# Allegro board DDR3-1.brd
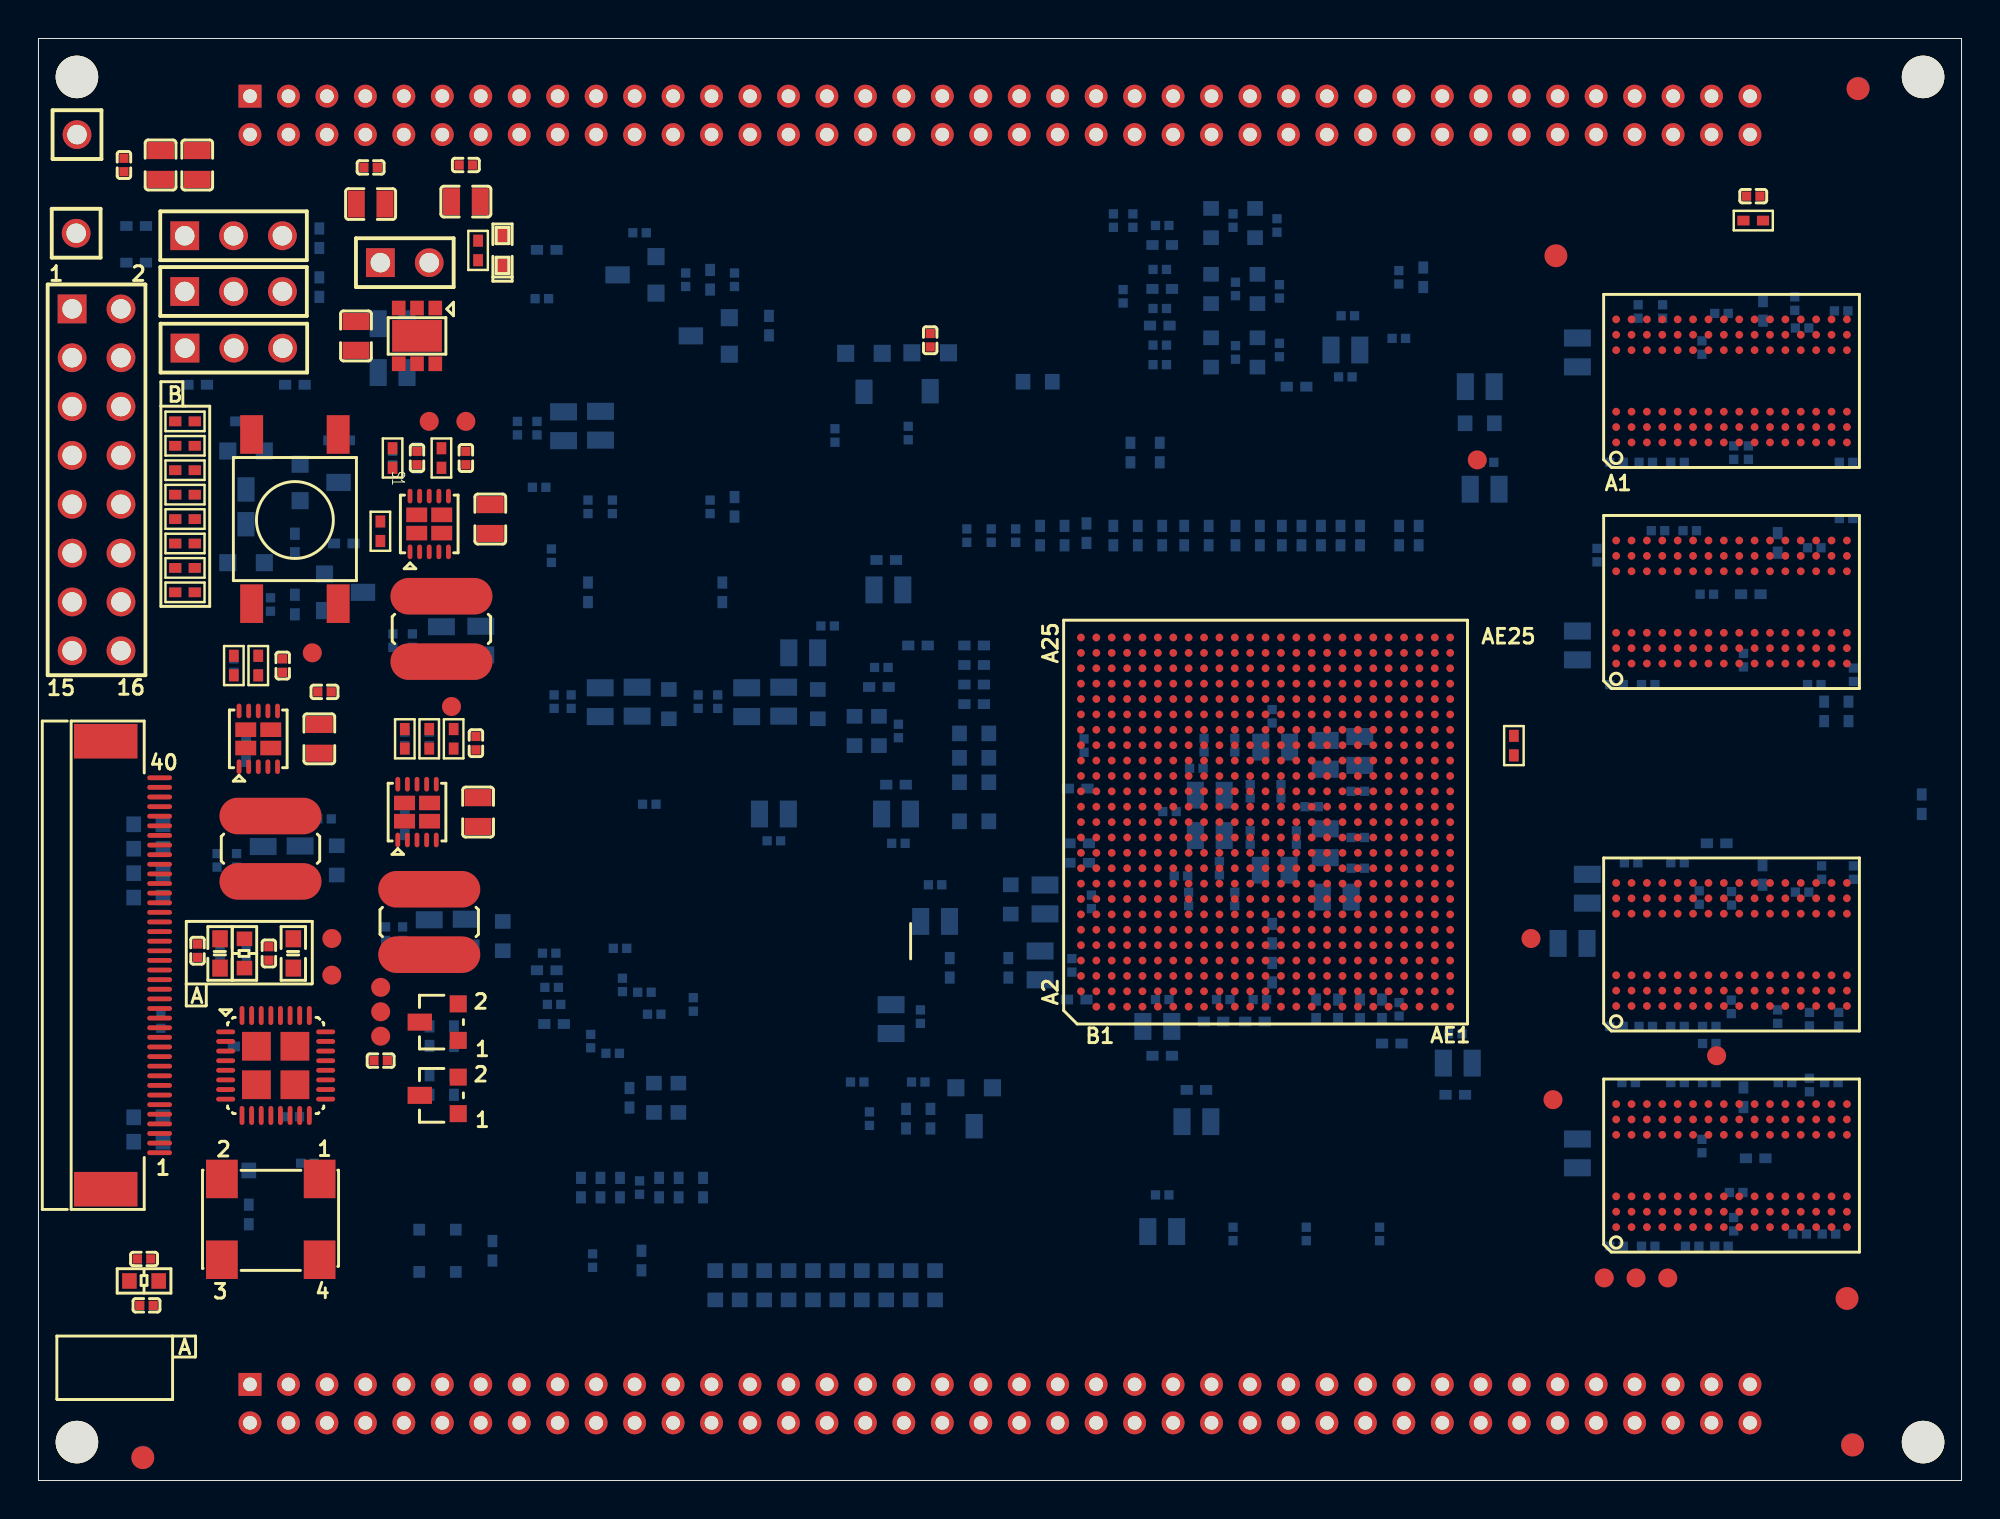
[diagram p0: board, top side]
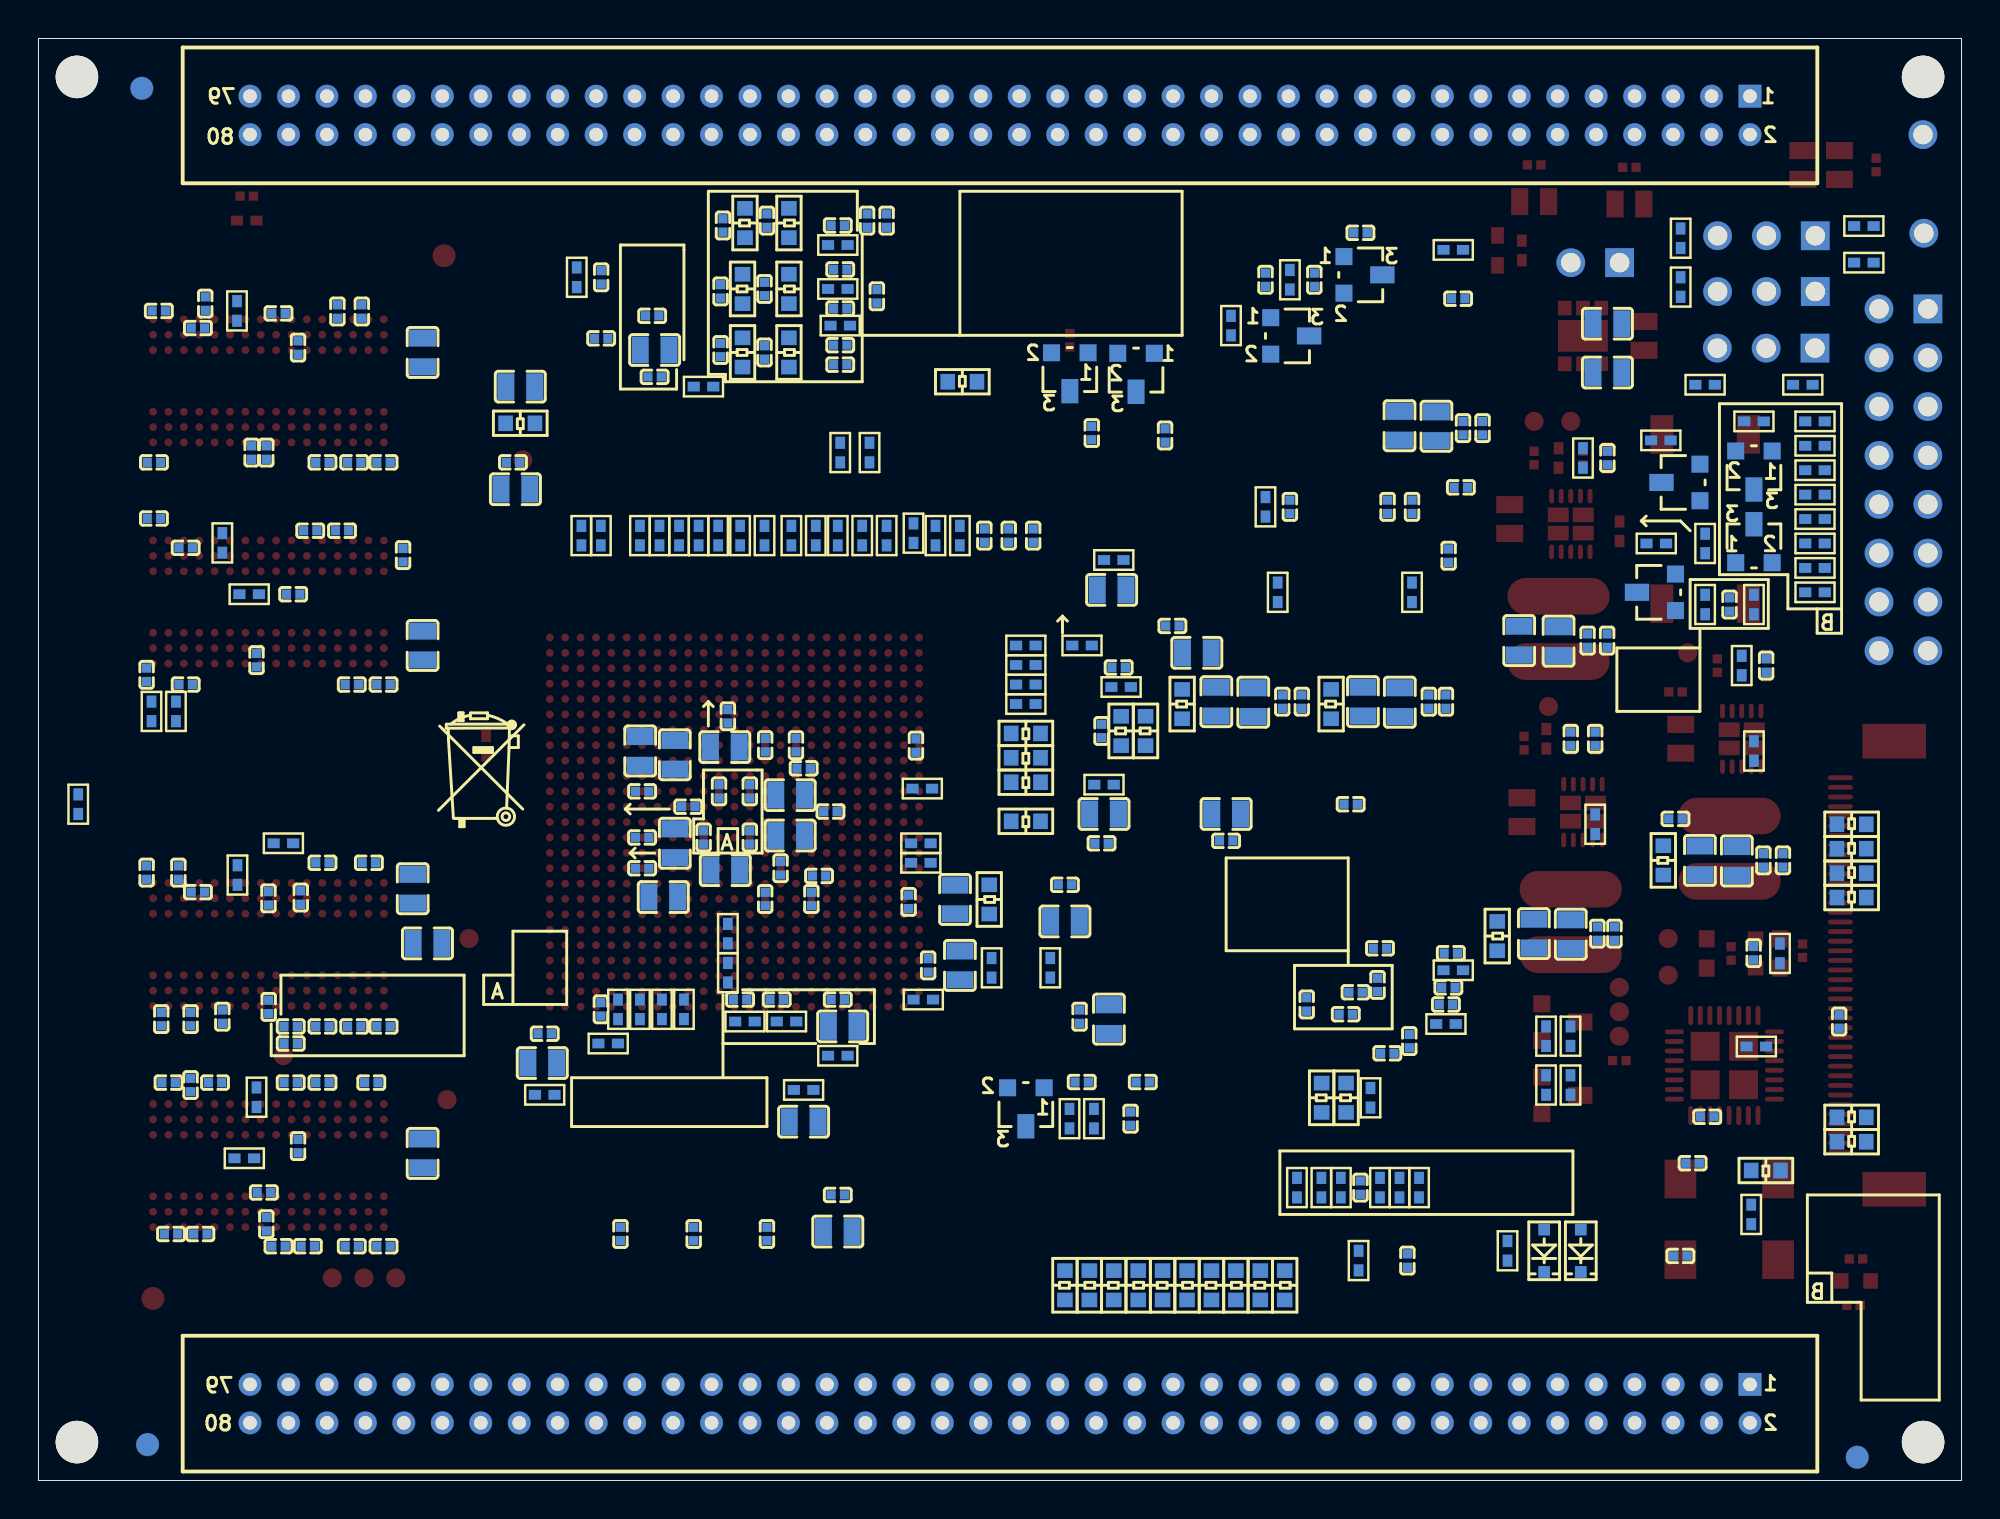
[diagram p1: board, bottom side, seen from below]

Outline 100 x 75 mm; copper layers: TOP, GND02, ART03, ART04, POWER05, ART06, GND07, BOTTOM. Coordinates in mm from the lower left corner of the outline.
Outline path: 0,75 0,0 ; 0,75 100,75 ; 0,75 0,0 ; 0,75 100,75 ; 0,0 100,0 ; 0,0 100,0 ; 100,75 100,10 ; 100,75 100,10 ; 100,0 100,10 ; 100,0 100,10

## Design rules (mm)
net group $$$4775: nets $$$4775 FEC_LED2
net group $$$7162: nets $$$7162 EIM_DA9
net group $$$7165: nets $$$7165 EIM_DA10
net group $$$7169: nets $$$7169 EIM_DA11
net group $$$7174: nets $$$7174 EIM_DA12
net group $$$7178: nets $$$7178 EIM_DA13
net group $$$7181: nets $$$7181 EIM_DA14
net group $$$7221: nets $$$7221 EIM_DA7
net group $$$7224: nets $$$7224 EIM_DA6
net group $$$7229: nets $$$7229 EIM_DA5
net group $$$7232: nets $$$7232 EIM_DA4
net group $$$9613: nets $$$9613 I2S_MCLK
net group $$$13768: nets $$$13768 VCC_5V
net group $$$14220: nets 1V3_CORE $$$14220
net group $$$14478: nets $$$14478 PWR_ON_REQ
net group $$$14578: nets $$$14578 $$$14580
net group $$$15209: nets 1V3_CORE23 $$$15209
net group $$$15211: nets $$$15211 $$$15212
net group $$$15334: nets 1V5 $$$15334
net group $$$15336: nets $$$15336 $$$15337
net group $$$15341: nets $$$15341 $$$15342
net group $$$16549: nets 1V3_SOC $$$16549
net group $$$16551: nets $$$16551 $$$16552
net group $$$17806: nets $$$17806 $$$17810
net group $$$18139: nets $$$18139 $$$18147
net group $$$22462: nets 1V8 $$$22462
net group $$$26219: nets $$$26219 SD3_CLK
net group $$$26224: nets $$$26224 SD4_CLK
net group $$$26282: nets $$$26282 SD1_CLK
net group $$$27898: nets $$$27898 PWM2
net group $$$32498: nets $$$32498 MIC
net group CSPI1_SSS0: nets CSPI1_SSS0 EIM_EB2
net group CSPI2_SSS0: nets CSPI2_SSS0 EIM_RW
net group CSPI2_SSS1: nets CSPI2_SSS1 EIM_LBA
net group DIFFPAIR10: nets USBOTG_DN USBOTG_DP
net group DIFFPAIR13: nets SATA_RXM SATA_RXP
net group DIFFPAIR14: nets SATA_TXM SATA_TXP
net group DIFFPAIR15: nets USB_H1_DN USB_H1_DP
net group DIFFPAIR16: nets PCIE_RXM PCIE_RXP
net group DIFFPAIR17: nets PCIE_TXM PCIE_TXP
net group DIFFPAIR18: nets PCIE_CLK_N PCIE_CLK_P
net group DIFFPAIR19: nets HDMI_CLKM HDMI_CLKP
net group DIFFPAIR20: nets HDMI_D0M HDMI_D0P
net group DIFFPAIR21: nets HDMI_D1M HDMI_D1P
net group DIFFPAIR22: nets HDMI_D2M HDMI_D2P
net group DIFFPAIR23: nets FEC_RX+ FEC_RX-
net group DIFFPAIR24: nets FEC_TX+ FEC_TX-
net group DIFFPAIR25: nets LVDS0_TX0_N LVDS0_TX0_P
net group DIFFPAIR26: nets LVDS0_TX2_N LVDS0_TX2_P
net group DIFFPAIR27: nets LVDS0_TX1_N LVDS0_TX1_P
net group DIFFPAIR28: nets LVDS0_TX3_N LVDS0_TX3_P
net group DIFFPAIR29: nets EXP2_27 EXP2_28
net group DIFFPAIR30: nets EXP2_29 EXP2_30
net group DIFFPAIR31: nets EXP2_31 EXP2_32
net group DIFFPAIR32: nets EXP2_33 EXP2_34
net group DIFFPAIR33: nets EXP2_35 EXP2_36
net group DIFFPAIR34: nets UART4_RXD UART4_TXD
net group DIFFPAIR35: nets LVDS1_TX0_N LVDS1_TX0_P
net group DIFFPAIR36: nets UART5_RXD UART5_TXD
net group DIFFPAIR37: nets LVDS1_TX1_N LVDS1_TX1_P
net group DIFFPAIR38: nets I2C3_SCL I2C3_SDA
net group DIFFPAIR39: nets LVDS1_TX2_N LVDS1_TX2_P
net group DIFFPAIR40: nets GP7_05 GP7_13
net group DIFFPAIR41: nets LVDS1_CLK_N LVDS1_CLK_P
net group DIFFPAIR42: nets LVDS1_TX3_N LVDS1_TX3_P
net group DIFFPAIR43: nets GP4_14 GP4_15
net group DIFFPAIR44: nets LVDS0_CLK_N LVDS0_CLK_P
net group SD1_CMD: nets SD1_CMD VCC_SD1
net group USB5V: nets USB5V USBH1_VBUS
net group 1V1: nets 1V1 HDMI_VP PCIE_VP PLL_1V1 SATA_VP
net group 2V5: nets 2V5 HDMI_VPH LVDS_2V5 PCIE_VPH SATA_VPH VCC_MIPI VDDHIGH_2V5
net group 5V_VGA: nets 5V_VGA DDC_SCL DDC_SDA
net group $$$12609: nets $$$6667 $$$6703 $$$9280 $$$12609 BATTERY VSNVS_3V0
net group $$$17664: nets $$$17664 $$$18017 I2C1_SCL I2C1_SDA NVCC_CSI
net group $$$22838: nets $$$22838 $$$22839 $$$22840
net group $$$24067: nets $$$3367 $$$24067 EIM_EB1 FEC_MDIO FEC_RST# VCC_FEC
net group $$$26032: nets $$$26032 $$$26035 USB5V_OTG
net group SD3_CD#: nets SD3_CD# SD3_CMD VCC_SD3

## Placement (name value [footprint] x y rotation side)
C1  CCAP  [C0805]  60.91 35.65 0 bottom
C2  CCAP  [C0402]  63.01 35.84 270 bottom
C3  CCAP  [C0402]  64.61 35.84 270 bottom
C4  CCAP  [C0402]  87.52 12.19 180 bottom
C5  CCAP  [C0402]  86.88 23.62 0 bottom
C6  CCAP  [C0805]  60.91 33.55 0 bottom
C7  CCAP  [C0805]  79.77 27.94 180 bottom
C8  CCAP  [C0402]  63.01 33.44 90 bottom
C9  CCAP  [C0402]  65.41 33.44 90 bottom
C10  CCAP  [C0402]  86.88 22.73 0 bottom
C11  CCAP  [C0402]  91.33 61.21 270 bottom
C12  CCAP  [C0805]  67.51 30.34 180 bottom
C13  CCAP  [C0402]  62.21 30.25 90 bottom
C14  CCAP  [C0402]  14.87 34.41 0 bottom
C15  CCAP  [C0402]  93.23 20.7 0 bottom
C16  CCAP  [C0402]  85.23 20.7 180 bottom
C17  CCAP  [C0805]  64.28 31.74 180 bottom
C18  CCAP  [C0805]  38.24 34.67 180 bottom
C19  CCAP  [C0402]  61.41 31.84 90 bottom
C20  CCAP  [C0402]  38.24 33.27 180 bottom
C21  CCAP  [C0402]  92.09 20.57 270 bottom
C22  CCAP  [C0402]  85.23 32.13 180 bottom
C23  CCAP  [C0805]  66.91 37.74 270 bottom
C24  CCAP  [C0805]  39.77 43.05 0 bottom
C25  CCAP  [C0402]  60.21 37.04 0 bottom
C26  CCAP  [C0402]  41.04 44.45 0 bottom
C27  CCAP  [C0402]  86.88 20.7 0 bottom
C28  CCAP  [C0402]  85.23 23.62 0 bottom
C29  CCAP  [C0805]  64.31 38.14 180 bottom
C31  CCAP  [C0402]  62.21 38.25 270 bottom
C32  CCAP  [C0402]  60.61 38.25 270 bottom
C33  CCAP  [C0402]  82.82 32.13 0 bottom
C34  CCAP  [C0402]  86.36 30.32 270 bottom
C35  CCAP  [C0805]  66.91 33.14 90 bottom
C36  CCAP  [C0805]  75.2 51.56 180 bottom
C37  CCAP  [C0402]  66.21 35.04 0 bottom
C38  CCAP  [C0402]  75.33 52.95 180 bottom
C39  CCAP  [C0402]  83.71 41.4 180 bottom
C41  CCAP  [C0805]  60.21 18.66 180 bottom
C42  CCAP  [C0402]  59.81 30.25 90 bottom
C44  CCAP  [C0402]  59.41 31.44 0 bottom
C47  CCAP  [C0402]  90.82 20.7 180 bottom
C48  CCAP  [C0402]  91.71 30.6 180 bottom
C49  CCAP  [C0402]  91.71 59.94 180 bottom
C50  CCAP  [C0402]  92.34 48.51 180 bottom
C51  CCAP  [C0402]  88.15 53.46 90 bottom
C52  CCAP  [C0402]  88.66 42.67 270 bottom
C53  CCAP  [C0402]  88.28 14.98 0 bottom
C54  CCAP  [C0402]  86.5 17.39 90 bottom
C55  CCAP  [C0402]  82.69 20.7 0 bottom
C56  CCAP  [C0402]  93.11 12.82 0 bottom
C57  CCAP  [C0402]  91.58 12.82 0 bottom
C58  CCAP  [C0402]  88.15 13.33 90 bottom
C59  CCAP  [C0402]  85.99 12.19 180 bottom
C60  CCAP  [C0402]  82.06 12.19 180 bottom
C61  CCAP  [C0402]  83.71 12.19 180 bottom
C62  CCAP  [C0805]  80.02 17.01 90 bottom
C63  CCAP  [C0402]  94.38 31.62 90 bottom
C64  CCAP  [C0402]  92.72 31.62 90 bottom
C65  CCAP  [C0402]  90.44 24.13 90 bottom
C66  CCAP  [C0402]  93.61 24 90 bottom
C67  CCAP  [C0402]  92.09 24 90 bottom
C68  CCAP  [C0402]  88.03 24.63 90 bottom
C69  CCAP  [C0402]  83.58 23.62 180 bottom
C70  CCAP  [C0402]  82.06 23.62 180 bottom
C71  CCAP  [C0402]  88.04 30.28 90 bottom
C72  CCAP  [C0805]  80.54 30.78 270 bottom
C73  CCAP  [C0402]  92.34 41.4 180 bottom
C74  CCAP  [C0402]  93.99 50.03 180 bottom
C75  CCAP  [C0402]  94.38 41.91 270 bottom
C76  CCAP  [C0402]  85.87 49.4 180 bottom
C77  CCAP  [C0402]  86.76 46.1 180 bottom
C78  CCAP  [C0402]  82.06 41.4 180 bottom
C79  CCAP  [C0402]  84.22 49.4 0 bottom
C80  CCAP  [C0402]  81.04 48.13 270 bottom
C81  CCAP  [C0402]  93.99 52.95 180 bottom
C82  CCAP  [C0805]  80.02 43.43 270 bottom
C83  CCAP  [C0402]  82.06 52.95 180 bottom
C84  CCAP  [C0402]  83.58 52.95 180 bottom
C85  CCAP  [C0402]  85.23 52.95 0 bottom
C86  CCAP  [C0402]  88.91 53.46 90 bottom
C87  CCAP  [C0402]  93.74 60.83 180 bottom
C88  CCAP  [C0402]  87.52 60.7 0 bottom
C89  CCAP  [C0402]  86.5 58.92 270 bottom
C90  CCAP  [C0402]  84.45 60.8 270 bottom
C91  CCAP  [C0402]  83.19 60.8 270 bottom
C92  CCAP  [C0805]  80.02 58.67 90 bottom
C93  CCAP  [C0402]  68.61 35.84 180 bottom
C94  CCAP  [C0402]  68.61 33.44 180 bottom
C95  CCAP  [C0402]  68.61 31.84 180 bottom
C99  CCAP  [C0805]  68.71 37.95 270 bottom
C100  CCAP  [C0402]  54.37 38.22 270 bottom
C101  CCAP  [C0402]  44.72 38.98 90 bottom
C102  CCAP  [C0402]  58.82 34.79 180 bottom
C103  CCAP  [C0402]  26.68 25.65 0 bottom
C104  CCAP  [C0402]  31.51 25.4 180 bottom
C105  CCAP  [C0402]  34.05 24.76 270 bottom
C106  CCAP  [C0402]  31.26 15.24 90 bottom
C107  CCAP  [C0402]  28.72 22.86 90 bottom
C108  CCAP  [C0402]  31.76 35.17 180 bottom
C109  CCAP  [C0402]  30.24 27.68 0 bottom
C110  CCAP  [C0402]  26.81 24.76 0 bottom
C111  CCAP  [C0402]  26.56 27.43 0 bottom
C112  CCAP  [C0402]  30.37 25.78 90 bottom
C113  CCAP  [C0402]  32.02 24.25 0 bottom
C114  CCAP  [C0402]  29.86 22.22 0 bottom
C115  CCAP  [C0805]  44.2 46.32 0 bottom
C116  CCAP  [C0402]  48.27 49.14 270 bottom
C117  CCAP  [C0402]  50.81 49.14 270 bottom
C118  CCAP  [C0402]  49.54 49.14 270 bottom
C120  CCAP  [C0402]  65.93 12.82 90 bottom
C122  CCAP  [C0402]  62.12 12.82 90 bottom
C124  CCAP  [C0402]  69.74 12.82 90 bottom
C126  CCAP  [C0402]  64.15 39.75 90 bottom
C127  CCAP  [C0402]  63.51 25.01 0 bottom
C128  CCAP  [C0805]  73.8 21.71 180 bottom
C129  CCAP  [C0402]  73.67 23.24 180 bottom
C130  CCAP  [C0402]  67.96 57.4 180 bottom
C131  CCAP  [C0402]  43.83 42.29 0 bottom
C132  CCAP  [C0402]  61.61 25.01 180 bottom
C133  CCAP  [C0805]  58.18 23.62 0 bottom
C134  CCAP  [C0402]  58.43 25.01 0 bottom
C135  CCAP  [C0805]  52.34 30.22 270 bottom
C136  CCAP  [C0402]  54.75 30.09 270 bottom
C137  CCAP  [C0805]  52.08 26.79 90 bottom
C138  CCAP  [C0402]  53.74 26.79 90 bottom
C139  CCAP  [C0805]  74.94 56.89 0 bottom
C140  CCAP  [C0402]  70.74 59.4 0 bottom
C141  CCAP  [C0402]  70.74 62.58 90 bottom
C144  CCAP  [C0402]  68.09 60.57 180 bottom
C145  CCAP  [C0805]  67.96 58.8 180 bottom
C152  CCAP  [C0402]  89.17 66.8 0 top
C153  CCAP  [C0805]  58.43 12.95 180 bottom
C154  CCAP  [C0402]  58.43 14.85 180 bottom
C155  CCAP  [C0805]  44.59 34.67 0 bottom
C156  CCAP  [C0402]  44.72 33.14 0 bottom
C157  CCAP  [C0805]  46.62 29.08 0 bottom
C158  CCAP  [C0402]  46.62 30.98 0 bottom
C159  CCAP  [C0402]  45.75 20.73 180 bottom
C160  CCAP  [C0402]  43.21 18.82 270 bottom
C161  CCAP  [C0402]  42.57 20.73 180 bottom
C162  CCAP  [C0402]  70.75 24.51 270 bottom
C163  CCAP  [C0402]  36.19 62.45 270 bottom
C164  CCAP  [C0805]  44.34 24 270 bottom
C165  CCAP  [C0402]  45.86 24.13 270 bottom
C166  CCAP  [C0402]  6.36 23.87 90 bottom
C167  CCAP  [C0402]  31.26 64.89 180 bottom
C168  CCAP  [C0402]  33.65 62.45 90 bottom
C173  CCAP  [C0402]  55.89 65.53 270 bottom
C174  CCAP  [C0402]  56.91 65.53 270 bottom
C175  CCAP  [C0402]  58.31 58.03 0 bottom
C176  CCAP  [C0402]  58.31 60.96 0 bottom
C177  CCAP  [C0402]  56.4 61.59 270 bottom
C178  CCAP  [C0402]  58.31 59.05 0 bottom
C179  CCAP  [C0402]  62.24 58.67 270 bottom
C180  CCAP  [C0402]  64.53 58.8 90 bottom
C181  CCAP  [C0402]  58.31 62.99 0 bottom
C182  CCAP  [C0402]  62.24 61.97 270 bottom
C183  CCAP  [C0402]  64.53 61.84 90 bottom
C184  CCAP  [C0402]  58.43 65.27 0 bottom
C185  CCAP  [C0402]  62.12 65.53 270 bottom
C186  CCAP  [C0402]  64.4 65.27 90 bottom
C190  CCAP  [C0402]  46.37 59.3 270 top
C191  CCAP  [C0402]  41.42 54.35 90 bottom
C192  CCAP  [C0402]  45.23 54.48 90 bottom
C193  CCAP  [C0402]  14.62 11.68 180 bottom
C194  CCAP  [C0402]  13.22 18.92 180 bottom
C195  CCAP  [C0402]  13.98 16.51 180 bottom
C196  CCAP  [C0603]  13.25 27.41 270 top
C197  CCAP  [C0402]  10.81 27.43 270 bottom
C198  CCAP  [C0402]  11.98 27.41 270 top
C199  CCAP  [C0402]  8.27 27.55 270 top
C200  CCAP  [C0603]  9.44 27.41 270 top
C201  CCAP  [C0402]  17.79 21.84 180 top
C202  CCAP  [C0402]  5.62 9.11 0 top
C203  CCAP  [C0805]  17.27 66.39 0 top
C204  CCAP  [C0402]  17.27 68.29 0 top
C205  CCAP  [C0402]  4.44 68.42 90 top
C206  CCAP  [C0805]  6.35 68.42 90 top
C207  CCAP  [C0805]  8.25 68.42 90 top
C208  CCAP  [C0402]  22.22 68.42 0 top
C209  CCAP  [C0805]  22.22 66.51 0 top
C210  CCAP  [C0402]  5.49 11.52 180 top
C211  CCAP  [C0805]  16.51 59.53 90 top
C212  CCAP  [C0805]  18.41 60.16 0 bottom
C213  CCAP  [C0805]  18.41 57.62 0 bottom
C214  CCAP  [C0402]  12.06 45.56 90 bottom
C215  CCAP  [C0402]  28.82 11.44 90 bottom
C218  CCAP  [C0402]  26.81 40.51 270 bottom
C219  CCAP  [C0402]  27.7 40.51 270 bottom
C220  CCAP  [C0805]  29.21 40.48 270 bottom
C221  CCAP  [C0805]  31.13 40.51 270 bottom
C222  CCAP  [C0402]  29.84 50.64 90 bottom
C223  CCAP  [C0402]  28.57 50.64 90 bottom
C224  CCAP  [C0805]  14.6 38.57 90 top
C225  CCAP  [C0402]  14.87 41.02 180 top
C226  CCAP  [C0402]  10.3 32.25 270 bottom
C227  CCAP  [C0402]  9.29 32.25 270 bottom
C228  CCAP  [C0805]  11.68 32.22 270 bottom
C229  CCAP  [C0805]  13.6 32.25 270 bottom
C230  CCAP  [C0402]  12.7 42.38 90 top
C231  CCAP  [C0402]  10.16 42.38 90 bottom
C234  CCAP  [C0402]  35.32 40.51 270 bottom
C235  CCAP  [C0402]  34.3 40.51 270 bottom
C236  CCAP  [C0805]  36.83 40.48 270 bottom
C237  CCAP  [C0805]  38.75 40.51 270 bottom
C239  CCAP  [C0402]  34.92 50.64 90 bottom
C240  CCAP  [C0805]  22.86 34.76 90 top
C241  CCAP  [C0402]  22.75 38.35 270 top
C242  CCAP  [C0402]  18.94 28.44 270 bottom
C243  CCAP  [C0402]  18.05 28.44 270 bottom
C244  CCAP  [C0805]  20.32 28.41 270 bottom
C245  CCAP  [C0805]  22.24 28.44 270 bottom
C246  CCAP  [C0402]  20.32 38.57 90 bottom
C247  CCAP  [C0402]  19.05 38.57 90 bottom
C248  CCAP  [C0805]  23.49 50 90 top
C249  CCAP  [C0402]  22.22 53.18 270 top
C250  CCAP  [C0402]  18.43 43.68 270 bottom
C251  CCAP  [C0402]  19.45 43.68 270 bottom
C252  CCAP  [C0805]  20.95 43.65 270 bottom
C253  CCAP  [C0805]  23 43.68 270 bottom
C254  CCAP  [C0402]  19.68 53.18 90 top
C255  CCAP  [C0402]  18.41 53.18 90 bottom
C257  CCAP  [C0402]  26.18 61.46 180 bottom
C258  CCAP  [C0402]  25.92 54.73 270 bottom
C259  CCAP  [C0402]  24.91 54.73 270 bottom
C260  CCAP  [C0805]  27.3 54.83 270 bottom
C261  CCAP  [C0805]  29.22 54.86 270 bottom
C263  CCAP  [C0402]  26.03 51.66 180 bottom
C265  CCAP  [C0402]  26.67 48.1 90 bottom
D3  BAT54C  [SOT_23]  34.92 59.53 270 bottom
D8  BAT54C  [SOT_23]  42.93 57.62 0 bottom
D9  BAT54C  [SOT_23]  46.37 57.65 0 bottom
D10  _LED_2P_  [D0603]  24.13 63.97 90 top
D11  DIODE  [SOD_323]  19.8 11.95 90 bottom
D12  DIODE  [SOD_323]  21.7 11.95 90 bottom
FB1  FEBEAD  [R0603]  50.56 30.22 270 bottom
FB2  FEBEAD  [R0603]  74.94 54.99 0 bottom
FB3  FEBEAD  [R0603]  51.96 57.15 180 bottom
FB4  FEBEAD  [R0603]  5.49 10.38 0 top
FB5  FEBEAD  [R0603]  10.71 27.41 90 top
FM1  -  [FIDUCIALMARK]  94.34 1.85 0 top
FM2  -  [FIDUCIALMARK]  94.61 72.39 0 top
FM3  -  [FIDUCIALMARK]  5.43 1.19 0 top
FM4  -  [FIDUCIALMARK]  94.05 9.47 0 top
FM*  -  [unnamed]  78.91 63.7 0 top
FM*#2  -  [unnamed]  94.63 72.41 180 bottom
FM*#3  -  [unnamed]  5.43 1.22 180 bottom
FM*#4  -  [unnamed]  94.33 1.88 180 bottom
J1  _HDR254_2X8_  [HDR254_2X8_A]  1.75 60.93 270 top
J2  _HDR254_3_  [JP254_3]  7.62 58.89 0 top
J3  _HDR254_3_  [JP254_3]  7.61 64.74 0 top
J4  _HDR254_3_  [JP254_3]  7.61 61.84 0 top
J5  _HDR200_2X40_  [HDR200_2X40]  11 72 0 bottom
J6  _HDR200_2X40_  [HDR200_2X40]  11 5 0 bottom
J7  _FPC_40_  [FPC40_P0_5]  6.3 26.8 270 top
J8  _HDR254_2_  [JP254_2]  17.78 63.34 90 top
J9  _HDR254_1_  [JP254_1]  2.01 70 0 top
J10  _HDR254_1_  [JP254_1]  1.96 64.87 0 top
L1  FEBEAD  [R0603]  60.97 58.67 270 bottom
L2  FEBEAD  [R0603]  63.39 58.67 90 bottom
L3  FEBEAD  [R0603]  60.97 61.97 270 bottom
L4  FEBEAD  [R0603]  63.39 61.97 90 bottom
L5  FEBEAD  [R0603]  60.97 65.4 270 bottom
L6  FEBEAD  [R0603]  63.26 65.4 90 bottom
L8  _IND_SMD_  [IND_SMD_5050]  12.06 32.86 90 top
L10  _IND_SMD_  [IND_SMD_5050]  20.32 29.05 90 top
L11  _IND_SMD_  [IND_SMD_5050]  20.95 44.29 90 top
MH1  _MOUNT_HOLE_  [MTH_1P2_2]  2 73 0 top
MH2  _MOUNT_HOLE_  [MTH_1P2_2]  2 2 0 top
MH3  _MOUNT_HOLE_  [MTH_1P2_2]  98 2 0 top
MH4  _MOUNT_HOLE_  [MTH_1P2_2]  98 73 0 top
NOREF  -  [#2]  74.44 37.08 180 bottom
Q1  BAT54C  [SOT_23]  48.66 19.43 0 bottom
Q3  BAT54C  [SOT_23]  20.83 23.84 90 top
Q4  BAT54C  [SOT_23]  20.83 20.03 90 top
Q5  FDC697P  [SOT_6]  19.68 59.53 180 top
Q6  BAT54C  [SOT_23]  14.6 51.91 90 bottom
Q7  BAT54C  [SOT_23]  10.79 48.73 180 bottom
Q8  BAT54C  [SOT_23]  10.79 52.54 0 bottom
Q9  BAT54C  [SOT_23]  15.87 46.19 90 bottom
R1  FEBEAD  [R0603]  32.78 40.38 90 bottom
R2  FEBEAD  [R0603]  15.51 32.25 90 bottom
R3  FEBEAD  [R0603]  40.53 40.38 90 bottom
R4  RES  [R0402]  60.21 20.32 180 bottom
R9  RES  [R0402]  88.66 19.93 270 bottom
R10  RES  [R0402]  89.65 31.49 270 bottom
R11  RES  [R0402]  90.44 48.76 270 bottom
R12  RES  [R0402]  89.68 60.83 270 bottom
R13  RES  [R0402]  97.93 35.17 270 bottom
R14  RES  [R0402]  76.72 38.22 90 top
R15  RES  [R0402]  94.12 40 90 bottom
R16  RES  [R0402]  92.85 40 270 bottom
R17  FEBEAD  [R0603]  24.14 28.32 270 bottom
R18  RES  [R0402]  89.3 16.76 180 bottom
R19  RES  [R0402]  89.04 46.1 180 bottom
R20  RES  [R0402]  48.66 41.4 180 bottom
R22  RES  [R0402]  48.66 40.38 180 bottom
R23  FEBEAD  [R0603]  48.66 38.86 0 bottom
R24  FEBEAD  [R0603]  48.66 37.59 0 bottom
R25  FEBEAD  [R0603]  43.7 38.98 90 bottom
R26  FEBEAD  [R0603]  42.43 38.98 90 bottom
R27  FEBEAD  [R0603]  48.66 34.29 0 bottom
R28  FEBEAD  [R0603]  48.66 36.32 0 bottom
R29  RES  [R0402]  26.43 26.54 0 bottom
R30  RES  [R0402]  30.73 19.91 270 bottom
R31  FEBEAD  [R0603]  33.27 19.91 90 bottom
R32  FEBEAD  [R0603]  32 19.91 90 bottom
R33  RES  [R0402]  26.81 23.74 0 bottom
R34  RES  [R0402]  29.22 15.24 270 bottom
R35  RES  [R0402]  30.24 15.24 270 bottom
R36  RES  [R0402]  32.27 15.24 270 bottom
R37  RES  [R0402]  33.29 15.24 270 bottom
R38  RES  [R0402]  28.21 15.24 270 bottom
R39  RES  [R0402]  34.56 15.24 270 bottom
R40  RES  [R0402]  67.71 49.14 90 bottom
R41  RES  [R0402]  53.35 49.14 90 bottom
R44  RES  [R0402]  54.04 35.99 180 bottom
R45  RES  [R0402]  48.66 42.41 180 bottom
R46  RES  [R0402]  44.08 47.87 0 bottom
R50  RES  [R0402]  53.99 25.01 0 bottom
R53  RES  [R0402]  45.73 43.43 0 bottom
R60  RES  [R0402]  63.26 23.87 0 bottom
R61  RES  [R0402]  73.67 20.06 180 bottom
R62  RES  [R0402]  64.15 28.44 270 bottom
R63  RES  [R0402]  64.15 26.41 90 bottom
R64  RES  [R0402]  65.42 56.89 0 bottom
R65  RES  [R0402]  43.7 41.27 0 bottom
R66  RES  [R0402]  61.1 23.87 180 bottom
R67  RES  [R0402]  58.43 22.09 0 bottom
R68  RES  [R0402]  50.43 26.67 90 bottom
R70  RES  [R0402]  70.75 49.14 90 bottom
R71  RES  [R0402]  68.72 49.14 270 bottom
R77  RES  [R0402]  72.01 62.58 270 bottom
R82  RES  [R0402]  89.17 65.53 180 top
R83  RES  [R0402]  44.59 36.19 0 bottom
R84  RES  [R0402]  47.39 26.67 90 bottom
R85  RES  [R0402]  54.12 32.13 180 bottom
R87  RES  [R0402]  45.11 18.82 90 bottom
R88  RES  [R0402]  46.38 18.82 90 bottom
R89  RES  [R0402]  70.37 22.73 0 bottom
R90  RES  [R0402]  37.99 60.07 90 bottom
R92  RES  [R0402]  34.92 62.45 270 bottom
R93  RES  [R0402]  54.12 33.14 180 bottom
R96  RES  [R0402]  69.86 24.51 90 bottom
R97  RES  [R0402]  68.72 24.51 90 bottom
R98  RES  [R0402]  67.58 24.51 90 bottom
R99  RES  [R0402]  66.44 24.51 90 bottom
R107  RES  [R0402]  56.78 53.46 270 bottom
R108  RES  [R0402]  60.85 49.14 270 bottom
R109  RES  [R0402]  58.31 53.46 270 bottom
R110  RES  [R0402]  62.24 49.14 270 bottom
R111  RES  [R0402]  7.62 52.54 180 bottom
R112  RES  [R0402]  7.62 52.54 180 top
R113  RES  [R0402]  7.62 55.08 180 bottom
R114  RES  [R0402]  7.62 55.08 180 top
R116  RES  [R0402]  65.67 49.14 90 bottom
R118  RES  [R0402]  7.62 46.19 180 bottom
R119  RES  [R0402]  7.62 46.19 180 top
R120  RES  [R0402]  7.62 48.73 180 bottom
R121  RES  [R0402]  7.62 48.73 180 top
R125  RES  [R0402]  58.43 49.14 270 bottom
R127  RES  [R0402]  55.89 49.14 270 bottom
R128  RES  [R0402]  57.16 49.14 270 bottom
R130  RES  [R0402]  54.5 49.27 270 bottom
R133  RES  [R0402]  59.58 49.14 270 bottom
R134  RES  [R0402]  63.51 49.14 270 bottom
R136  RES  [R0402]  48.66 43.43 0 bottom
R137  RES  [R0402]  52.08 49.14 270 bottom
R138  RES  [R0402]  7.62 51.27 0 bottom
R139  RES  [R0402]  7.62 51.27 0 top
R140  RES  [R0402]  7.62 53.81 0 bottom
R141  RES  [R0402]  7.62 53.81 0 top
R142  RES  [R0402]  66.69 49.14 270 bottom
R144  RES  [R0402]  7.62 47.46 0 bottom
R145  RES  [R0402]  7.62 47.46 0 top
R146  RES  [R0402]  7.62 50 0 bottom
R147  RES  [R0402]  7.62 50 0 top
R148  RES  [R0402]  64.66 49.14 270 bottom
R149  RES  [R0402]  8.25 56.99 0 bottom
R150  RES  [R0402]  5.08 65.24 180 bottom
R151  RES  [R0402]  5.08 63.34 180 bottom
R152  RES  [R0402]  13.33 56.99 180 bottom
R153  RES  [R0402]  14.6 64.61 90 bottom
R154  RES  [R0402]  14.6 62.07 270 bottom
R155  RES  [R0402]  58.31 60.07 0 bottom
R156  RES  [R0402]  58.43 61.97 0 bottom
R157  RES  [R0402]  58.43 64.26 0 bottom
R159  RES  [R0402]  21.6 23.11 90 bottom
R160  RES  [R0402]  20.33 23.11 270 bottom
R161  RES  [R0402]  21.6 20.57 270 bottom
R162  RES  [R0402]  20.33 20.57 90 bottom
R163  RES  [R0402]  10.67 22.57 0 bottom
R164  RES  [R0402]  10.94 13.84 90 bottom
R165  RES  [R0402]  9.44 27.41 270 bottom
R171  FEBEAD  [R0603]  35.19 10.16 270 bottom
R172  FEBEAD  [R0603]  37.73 10.16 270 bottom
R173  FEBEAD  [R0603]  40.27 10.16 270 bottom
R174  FEBEAD  [R0603]  42.81 10.16 270 bottom
R175  FEBEAD  [R0603]  45.35 10.16 270 bottom
R181  FEBEAD  [R0603]  36.46 10.16 90 bottom
R182  FEBEAD  [R0603]  39 10.16 90 bottom
R183  FEBEAD  [R0603]  41.54 10.16 90 bottom
R184  FEBEAD  [R0603]  44.08 10.16 90 bottom
R185  FEBEAD  [R0603]  46.62 10.16 90 bottom
R186  FEBEAD  [R0603]  5.71 17.62 180 bottom
R187  FEBEAD  [R0603]  5.71 18.89 180 bottom
R188  FEBEAD  [R0603]  5.71 30.32 180 bottom
R189  FEBEAD  [R0603]  5.71 31.59 180 bottom
R190  FEBEAD  [R0603]  5.71 32.86 180 bottom
R191  FEBEAD  [R0603]  5.71 34.13 180 bottom
R192  RES  [R0402]  15.64 54.1 0 bottom
R193  RES  [R0402]  13.33 48.73 90 bottom
R194  RES  [R0402]  15.87 48.73 0 bottom
R195  RES  [R0402]  13.33 45.56 270 bottom
R196  RES  [R0402]  10.79 55.08 180 bottom
R197  RES  [R0402]  10.79 45.56 270 bottom
R198  RES  [R0402]  22.86 63.97 90 top
R199  RES  [R0402]  23.61 11.95 270 bottom
R200  RES  [R0402]  31.36 11.44 90 bottom
R204  RES  [R0402]  28.57 46.19 270 bottom
R205  RES  [R0402]  11.43 42.38 90 top
R206  RES  [R0402]  11.43 42.38 90 bottom
R207  RES  [R0402]  10.16 42.38 270 top
R208  RES  [R0402]  10.79 37.94 270 bottom
R209  RES  [R0402]  36.19 50.64 90 bottom
R212  RES  [R0402]  35.56 46.19 270 bottom
R213  RES  [R0402]  20.32 38.57 90 top
R214  RES  [R0402]  21.59 38.57 90 top
R215  RES  [R0402]  19.05 38.57 270 top
R216  RES  [R0402]  19.05 34.13 270 bottom
R217  RES  [R0402]  19.68 53.18 90 bottom
R218  RES  [R0402]  20.95 53.18 90 top
R219  RES  [R0402]  18.41 53.18 270 top
R220  RES  [R0402]  17.78 49.37 270 top
R222  RES  [R0402]  26.43 64 0 bottom
R223  FEBEAD  [R0603]  10.17 16.12 0 bottom
R224  RES  [R0402]  87.26 33.14 180 bottom
R226  RES  [R0402]  71.77 49.14 90 bottom
S1  _TACT_4P_PUSHON_  [TACT_4P_PUSHON]  13.33 50 270 top
TP1  -  [TESTPOINT]  77.61 28.19 0 top
TP3  -  [TESTPOINT]  78.75 19.81 0 top
TP5  -  [TESTPOINT]  74.82 53.08 0 top
TP9  -  [TESTPOINT]  83.07 10.54 0 top
TP10  -  [TESTPOINT]  84.72 10.54 0 top
TP11  -  [TESTPOINT]  87.26 22.09 0 top
TP12  -  [TESTPOINT]  81.42 10.54 0 top
TP17  -  [TESTPOINT]  15.25 28.19 0 top
TP18  -  [TESTPOINT]  15.25 26.28 0 top
TP19  -  [TESTPOINT]  17.79 25.65 0 top
TP20  -  [TESTPOINT]  17.79 23.11 0 top
TP21  -  [TESTPOINT]  17.79 24.38 0 top
TP23  -  [TESTPOINT]  14.24 43.05 90 top
TP26  -  [TESTPOINT]  21.48 40.25 90 top
TP28  -  [TESTPOINT]  20.32 55.08 90 top
TP30  -  [TESTPOINT]  22.22 55.08 90 top
U1  IMX6Q  [IMX6Q_PBGA624_P0_8]  63.81 34.25 90 top
U2  _DDR3_16BIT_  [BGA96_P0_8]  88.04 16.38 90 top
U3  _DDR3_16BIT_  [BGA96_P0_8]  88.04 27.88 90 top
U4  _DDR3_16BIT_  [BGA96_P0_8]  88.04 45.69 90 top
U5  _DDR3_16BIT_  [BGA96_P0_8]  88.04 57.19 90 top
U11  BAT54C  [SOT_23]  31.11 62.7 270 bottom
U15  ALC5633Q  [QFN32]  12.33 21.59 90 top
U16  _OSC_4_  [OSC4_751]  12.08 13.58 180 top
U19  RT8055  [DFN_10_3X3]  11.43 38.57 0 top
U21  RT8055  [DFN_10_3X3]  19.68 34.76 0 top
U22  RT8055  [DFN_10_3X3]  20.32 49.75 0 top

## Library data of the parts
C1 C6 C7 C12 C17 C18 C23 C24 C29 C35 C36 C41 C62 C72 C82 C92 C99 C115 C128 C133 C135 C137 C139 C145 C153 C155 C157 C164 C203 C206 C207 C209 C211-C213 C220 C221 C224 C228 C229 C236 C237 C240 C244 C245 C248 C252 C253 C260 C261 = C0805
C2-C5 C8-C11 C13-C16 C19-C22 C25-C28 C31-C34 C37-C39 C42 C44 C47-C61 C63-C71 C73-C81 C83-C91 C93-C95 C100-C114 C116-C118 C120 C122 C124 C126 C127 C129-C132 C134 C136 C138 C140 C141 C144 C152 C154 C156 C158-C163 C165-C168 C173-C186 C190-C195 C197-C199 C201 C202 C204 C205 C208 C210 C214 C215 C218 C219 C222 C223 C225-C227 C230 C231 C234 C235 C239 C241-C243 C246 C247 C249-C251 C254 C255 C257-C259 C263 C265 = C0402
C196 C200 = C0603
D3 D8 D9 Q1 Q3 Q4 Q6-Q9 U11 = SOT_23
D10 = D0603
D11 D12 = SOD_323
FB1-FB5 L1-L6 R1-R3 R17 R23-R28 R31 R32 R171-R175 R181-R191 R223 = R0603
FM1-FM4 = FIDUCIALMARK
J1 = HDR254_2X8_A
J2-J4 = JP254_3
J5 J6 = HDR200_2X40
J7 = FPC40_P0_5
J8 = JP254_2
J9 J10 = JP254_1
L8 L10 L11 = IND_SMD_5050
MH1-MH4 = MTH_1P2_2
Q5 = SOT_6
R4 R9-R16 R18-R20 R22 R29 R30 R33-R41 R44-R46 R50 R53 R60-R68 R70 R71 R77 R82-R85 R87-R90 R92 R93 R96-R99 R107-R114 R116 R118-R121 R125 R127 R128 R130 R133 R134 R136-R142 R144-R157 R159-R165 R192-R200 R204-R209 R212-R220 R222 R224 R226 = R0402: signal model: R0402_RES
S1 = TACT_4P_PUSHON
TP1 TP3 TP5 TP9-TP12 TP17-TP21 TP23 TP26 TP28 TP30 = TESTPOINT
U1 = IMX6Q_PBGA624_P0_8
U2-U5 = BGA96_P0_8
U15 = QFN32
U16 = OSC4_751
U19 U21 U22 = DFN_10_3X3

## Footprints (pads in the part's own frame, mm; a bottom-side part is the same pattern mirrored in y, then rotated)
BGA96_P0_8
  round 0.406 smd: A1(-3.2,6) A2(-2.4,6) A3(-1.6,6) A7(1.6,6) A8(2.4,6) A9(3.2,6) B1(-3.2,5.2) B2(-2.4,5.2) B3(-1.6,5.2) B7(1.6,5.2) B8(2.4,5.2) B9(3.2,5.2) C1(-3.2,4.4) C2(-2.4,4.4) C3(-1.6,4.4) C7(1.6,4.4) C8(2.4,4.4) C9(3.2,4.4) D1(-3.2,3.6) D2(-2.4,3.6) D3(-1.6,3.6) D7(1.6,3.6) D8(2.4,3.6) D9(3.2,3.6) E1(-3.2,2.8) E2(-2.4,2.8) E3(-1.6,2.8) E7(1.6,2.8) E8(2.4,2.8) E9(3.2,2.8) F1(-3.2,2) F2(-2.4,2) F3(-1.6,2) F7(1.6,2) F8(2.4,2) F9(3.2,2) G1(-3.2,1.2) G2(-2.4,1.2) G3(-1.6,1.2) G7(1.6,1.2) G8(2.4,1.2) G9(3.2,1.2) H1(-3.2,0.4) H2(-2.4,0.4) H3(-1.6,0.4) H7(1.6,0.4) H8(2.4,0.4) H9(3.2,0.4) J1(-3.2,-0.4) J2(-2.4,-0.4) J3(-1.6,-0.4) J7(1.6,-0.4) J8(2.4,-0.4) J9(3.2,-0.4) K1(-3.2,-1.2) K2(-2.4,-1.2) K3(-1.6,-1.2) K7(1.6,-1.2) K8(2.4,-1.2) K9(3.2,-1.2) L1(-3.2,-2) L2(-2.4,-2) L3(-1.6,-2) L7(1.6,-2) L8(2.4,-2) L9(3.2,-2) M1(-3.2,-2.8) M2(-2.4,-2.8) M3(-1.6,-2.8) M7(1.6,-2.8) M8(2.4,-2.8) M9(3.2,-2.8) N1(-3.2,-3.6) N2(-2.4,-3.6) N3(-1.6,-3.6) N7(1.6,-3.6) N8(2.4,-3.6) N9(3.2,-3.6) P1(-3.2,-4.4) P2(-2.4,-4.4) P3(-1.6,-4.4) P7(1.6,-4.4) P8(2.4,-4.4) P9(3.2,-4.4) R1(-3.2,-5.2) R2(-2.4,-5.2) R3(-1.6,-5.2) R7(1.6,-5.2) R8(2.4,-5.2) R9(3.2,-5.2) T1(-3.2,-6) T2(-2.4,-6) T3(-1.6,-6) T7(1.6,-6) T8(2.4,-6) T9(3.2,-6)
C0402
  rect 0.483x0.483 smd: 1(-0.35,0) 2(0.35,0)
C0603
  rect 0.889x0.813 smd: 1(-0.762,0) 2(0.762,0)
C0805
  rect 0.889x1.397 smd: 1(-0.75,0) 2(0.75,0)
D0603
  rect 0.864x0.66 smd: 1(-0.78,0) 2(0.78,0)
DFN_10_3X3
  oval 0.254x0.762 smd: 1(-1,-1.45) 2(-0.5,-1.45) 3(0,-1.45) 4(0.5,-1.45) 5(1,-1.45) 6(1,1.45) 7(0.5,1.45) 8(0,1.45) 9(-0.5,1.45) 10(-1,1.45)
  rect 1.092x0.762 smd: 11(-0.65,-0.475) 12(0.65,-0.475) 13(-0.65,0.475) 14(0.65,0.475)
FIDUCIALMARK
  round 1.194 smd: 1(0,0)
FPC40_P0_5
  oval 0.254x1.295 smd: 1(9.75,0) 2(9.25,0) 3(8.75,0) 4(8.25,0) 5(7.75,0) 6(7.25,0) 7(6.75,0) 8(6.25,0) 9(5.75,0) 10(5.25,0) 11(4.75,0) 12(4.25,0) 13(3.75,0) 14(3.25,0) 15(2.75,0) 16(2.25,0) 17(1.75,0) 18(1.25,0) 19(0.75,0) 20(0.25,0) 21(-0.25,0) 22(-0.75,0) 23(-1.25,0) 24(-1.75,0) 25(-2.25,0) 26(-2.75,0) 27(-3.25,0) 28(-3.75,0) 29(-4.25,0) 30(-4.75,0) 31(-5.25,0) 32(-5.75,0) 33(-6.25,0) 34(-6.75,0) 35(-7.25,0) 36(-7.75,0) 37(-8.25,0) 38(-8.75,0) 39(-9.25,0) 40(-9.75,0)
  rect 1.803x3.302 smd: 41(11.65,-2.8) 42(-11.65,-2.8)
HDR200_2X40
  rect 1.194x1.194 hole 0.711: 1(0,0)
  round 1.194 hole 0.711: 2(0,2) 3(2,0) 4(2,2) 5(4,0) 6(4,2) 7(6,0) 8(6,2) 9(8,0) 10(8,2) 11(10,0) 12(10,2) 13(12,0) 14(12,2) 15(14,0) 16(14,2) 17(16,0) 18(16,2) 19(18,0) 20(18,2) 21(20,0) 22(20,2) 23(22,0) 24(22,2) 25(24,0) 26(24,2) 27(26,0) 28(26,2) 29(28,0) 30(28,2) 31(30,0) 32(30,2) 33(32,0) 34(32,2) 35(34,0) 36(34,2) 37(36,0) 38(36,2) 39(38,0) 40(38,2) 41(40,0) 42(40,2) 43(42,0) 44(42,2) 45(44,0) 46(44,2) 47(46,0) 48(46,2) 49(48,0) 50(48,2) 51(50,0) 52(50,2) 53(52,0) 54(52,2) 55(54,0) 56(54,2) 57(56,0) 58(56,2) 59(58,0) 60(58,2) 61(60,0) 62(60,2) 63(62,0) 64(62,2) 65(64,0) 66(64,2) 67(66,0) 68(66,2) 69(68,0) 70(68,2) 71(70,0) 72(70,2) 73(72,0) 74(72,2) 75(74,0) 76(74,2) 77(76,0) 78(76,2) 79(78,0) 80(78,2)
HDR254_2X8_A
  rect 1.499x1.499 hole 1.016: 1(0,0)
  round 1.499 hole 1.016: 2(0,2.54) 3(2.54,0) 4(2.54,2.54) 5(5.08,0) 6(5.08,2.54) 7(7.62,0) 8(7.62,2.54) 9(10.16,0) 10(10.16,2.54) 11(12.7,0) 12(12.7,2.54) 13(15.24,0) 14(15.24,2.54) 15(17.78,0) 16(17.78,2.54)
IMX6Q_PBGA624_P0_8
  round 0.406 smd: A2(-8.8,9.6) A3(-8,9.6) A4(-7.2,9.6) A5(-6.4,9.6) A6(-5.6,9.6) A7(-4.8,9.6) A8(-4,9.6) A9(-3.2,9.6) A10(-2.4,9.6) A11(-1.6,9.6) A12(-0.8,9.6) A13(0,9.6) A14(0.8,9.6) A15(1.6,9.6) A16(2.4,9.6) A17(3.2,9.6) A18(4,9.6) A19(4.8,9.6) A20(5.6,9.6) A21(6.4,9.6) A22(7.2,9.6) A23(8,9.6) A24(8.8,9.6) A25(9.6,9.6) AA1(-9.6,-6.4) AA2(-8.8,-6.4) AA3(-8,-6.4) AA4(-7.2,-6.4) AA5(-6.4,-6.4) AA6(-5.6,-6.4) AA7(-4.8,-6.4) AA8(-4,-6.4) AA9(-3.2,-6.4) AA10(-2.4,-6.4) AA11(-1.6,-6.4) AA12(-0.8,-6.4) AA13(0,-6.4) AA14(0.8,-6.4) AA15(1.6,-6.4) AA16(2.4,-6.4) AA17(3.2,-6.4) AA18(4,-6.4) AA19(4.8,-6.4) AA20(5.6,-6.4) AA21(6.4,-6.4) AA22(7.2,-6.4) AA23(8,-6.4) AA24(8.8,-6.4) AA25(9.6,-6.4) AB1(-9.6,-7.2) AB2(-8.8,-7.2) AB3(-8,-7.2) AB4(-7.2,-7.2) AB5(-6.4,-7.2) AB6(-5.6,-7.2) AB7(-4.8,-7.2) AB8(-4,-7.2) AB9(-3.2,-7.2) AB10(-2.4,-7.2) AB11(-1.6,-7.2) AB12(-0.8,-7.2) AB13(0,-7.2) AB14(0.8,-7.2) AB15(1.6,-7.2) AB16(2.4,-7.2) AB17(3.2,-7.2) AB18(4,-7.2) AB19(4.8,-7.2) AB20(5.6,-7.2) AB21(6.4,-7.2) AB22(7.2,-7.2) AB23(8,-7.2) AB24(8.8,-7.2) AB25(9.6,-7.2) AC1(-9.6,-8) AC2(-8.8,-8) AC3(-8,-8) AC4(-7.2,-8) AC5(-6.4,-8) AC6(-5.6,-8) AC7(-4.8,-8) AC8(-4,-8) AC9(-3.2,-8) AC10(-2.4,-8) AC11(-1.6,-8) AC12(-0.8,-8) AC13(0,-8) AC14(0.8,-8) AC15(1.6,-8) AC16(2.4,-8) AC17(3.2,-8) AC18(4,-8) AC19(4.8,-8) AC20(5.6,-8) AC21(6.4,-8) AC22(7.2,-8) AC23(8,-8) AC24(8.8,-8) AC25(9.6,-8) AD1(-9.6,-8.8) AD2(-8.8,-8.8) AD3(-8,-8.8) AD4(-7.2,-8.8) AD5(-6.4,-8.8) AD6(-5.6,-8.8) AD7(-4.8,-8.8) AD8(-4,-8.8) AD9(-3.2,-8.8) AD10(-2.4,-8.8) AD11(-1.6,-8.8) AD12(-0.8,-8.8) AD13(0,-8.8) AD14(0.8,-8.8) AD15(1.6,-8.8) AD16(2.4,-8.8) AD17(3.2,-8.8) AD18(4,-8.8) AD19(4.8,-8.8) AD20(5.6,-8.8) AD21(6.4,-8.8) AD22(7.2,-8.8) AD23(8,-8.8) AD24(8.8,-8.8) AD25(9.6,-8.8) AE1(-9.6,-9.6) AE2(-8.8,-9.6) AE3(-8,-9.6) AE4(-7.2,-9.6) AE5(-6.4,-9.6) AE6(-5.6,-9.6) AE7(-4.8,-9.6) AE8(-4,-9.6) AE9(-3.2,-9.6) AE10(-2.4,-9.6) AE11(-1.6,-9.6) AE12(-0.8,-9.6) AE13(0,-9.6) AE14(0.8,-9.6) AE15(1.6,-9.6) AE16(2.4,-9.6) AE17(3.2,-9.6) AE18(4,-9.6) AE19(4.8,-9.6) AE20(5.6,-9.6) AE21(6.4,-9.6) AE22(7.2,-9.6) AE23(8,-9.6) AE24(8.8,-9.6) AE25(9.6,-9.6) B1(-9.6,8.8) B2(-8.8,8.8) B3(-8,8.8) B4(-7.2,8.8) B5(-6.4,8.8) B6(-5.6,8.8) B7(-4.8,8.8) B8(-4,8.8) B9(-3.2,8.8) B10(-2.4,8.8) B11(-1.6,8.8) B12(-0.8,8.8) B13(0,8.8) B14(0.8,8.8) B15(1.6,8.8) B16(2.4,8.8) B17(3.2,8.8) B18(4,8.8) B19(4.8,8.8) B20(5.6,8.8) B21(6.4,8.8) B22(7.2,8.8) B23(8,8.8) B24(8.8,8.8) B25(9.6,8.8) C1(-9.6,8) C2(-8.8,8) C3(-8,8) C4(-7.2,8) C5(-6.4,8) C6(-5.6,8) C7(-4.8,8) C8(-4,8) C9(-3.2,8) C10(-2.4,8) C11(-1.6,8) C12(-0.8,8) C13(0,8) C14(0.8,8) C15(1.6,8) C16(2.4,8) C17(3.2,8) C18(4,8) C19(4.8,8) C20(5.6,8) C21(6.4,8) C22(7.2,8) C23(8,8) C24(8.8,8) C25(9.6,8) D1(-9.6,7.2) D2(-8.8,7.2) D3(-8,7.2) D4(-7.2,7.2) D5(-6.4,7.2) D6(-5.6,7.2) D7(-4.8,7.2) D8(-4,7.2) D9(-3.2,7.2) D10(-2.4,7.2) D11(-1.6,7.2) D12(-0.8,7.2) D13(0,7.2) D14(0.8,7.2) D15(1.6,7.2) D16(2.4,7.2) D17(3.2,7.2) D18(4,7.2) D19(4.8,7.2) D20(5.6,7.2) D21(6.4,7.2) D22(7.2,7.2) D23(8,7.2) D24(8.8,7.2) D25(9.6,7.2) E1(-9.6,6.4) E2(-8.8,6.4) E3(-8,6.4) E4(-7.2,6.4) E5(-6.4,6.4) E6(-5.6,6.4) E7(-4.8,6.4) E8(-4,6.4) E9(-3.2,6.4) E10(-2.4,6.4) E11(-1.6,6.4) E12(-0.8,6.4) E13(0,6.4) E14(0.8,6.4) E15(1.6,6.4) E16(2.4,6.4) E17(3.2,6.4) E18(4,6.4) E19(4.8,6.4) E20(5.6,6.4) E21(6.4,6.4) E22(7.2,6.4) E23(8,6.4) E24(8.8,6.4) E25(9.6,6.4) F1(-9.6,5.6) F2(-8.8,5.6) F3(-8,5.6) F4(-7.2,5.6) F5(-6.4,5.6) F6(-5.6,5.6) F7(-4.8,5.6) F8(-4,5.6) F9(-3.2,5.6) F10(-2.4,5.6) F11(-1.6,5.6) F12(-0.8,5.6) F13(0,5.6) F14(0.8,5.6) F15(1.6,5.6) F16(2.4,5.6) F17(3.2,5.6) F18(4,5.6) F19(4.8,5.6) F20(5.6,5.6) F21(6.4,5.6) F22(7.2,5.6) F23(8,5.6) F24(8.8,5.6) F25(9.6,5.6) G1(-9.6,4.8) G2(-8.8,4.8) G3(-8,4.8) G4(-7.2,4.8) G5(-6.4,4.8) G6(-5.6,4.8) G7(-4.8,4.8) G8(-4,4.8) G9(-3.2,4.8) G10(-2.4,4.8) G11(-1.6,4.8) G12(-0.8,4.8) G13(0,4.8) G14(0.8,4.8) G15(1.6,4.8) G16(2.4,4.8) G17(3.2,4.8) G18(4,4.8) G19(4.8,4.8) G20(5.6,4.8) G21(6.4,4.8) G22(7.2,4.8) G23(8,4.8) G24(8.8,4.8) G25(9.6,4.8) H1(-9.6,4) H2(-8.8,4) H3(-8,4) H4(-7.2,4) H5(-6.4,4) H6(-5.6,4) H7(-4.8,4) H8(-4,4) H9(-3.2,4) H10(-2.4,4) H11(-1.6,4) H12(-0.8,4) H13(0,4) H14(0.8,4) H15(1.6,4) H16(2.4,4) H17(3.2,4) H18(4,4) H19(4.8,4) H20(5.6,4) H21(6.4,4) H22(7.2,4) H23(8,4) H24(8.8,4) H25(9.6,4) J1(-9.6,3.2) J2(-8.8,3.2) J3(-8,3.2) J4(-7.2,3.2) J5(-6.4,3.2) J6(-5.6,3.2) J7(-4.8,3.2) J8(-4,3.2) J9(-3.2,3.2) J10(-2.4,3.2) J11(-1.6,3.2) J12(-0.8,3.2) J13(0,3.2) J14(0.8,3.2) J15(1.6,3.2) J16(2.4,3.2) J17(3.2,3.2) J18(4,3.2) J19(4.8,3.2) J20(5.6,3.2) J21(6.4,3.2) J22(7.2,3.2) J23(8,3.2) J24(8.8,3.2) J25(9.6,3.2) K1(-9.6,2.4) K2(-8.8,2.4) K3(-8,2.4) K4(-7.2,2.4) K5(-6.4,2.4) K6(-5.6,2.4) K7(-4.8,2.4) K8(-4,2.4) K9(-3.2,2.4) K10(-2.4,2.4) K11(-1.6,2.4) K12(-0.8,2.4) K13(0,2.4) K14(0.8,2.4) K15(1.6,2.4) K16(2.4,2.4) K17(3.2,2.4) K18(4,2.4) K19(4.8,2.4) K20(5.6,2.4) K21(6.4,2.4) K22(7.2,2.4) K23(8,2.4) K24(8.8,2.4) K25(9.6,2.4) L1(-9.6,1.6) L2(-8.8,1.6) L3(-8,1.6) L4(-7.2,1.6) L5(-6.4,1.6) L6(-5.6,1.6) L7(-4.8,1.6) L8(-4,1.6) L9(-3.2,1.6) L10(-2.4,1.6) L11(-1.6,1.6) L12(-0.8,1.6) L13(0,1.6) L14(0.8,1.6) L15(1.6,1.6) L16(2.4,1.6) L17(3.2,1.6) L18(4,1.6) L19(4.8,1.6) L20(5.6,1.6) L21(6.4,1.6) L22(7.2,1.6) L23(8,1.6) L24(8.8,1.6) L25(9.6,1.6) M1(-9.6,0.8) M2(-8.8,0.8) M3(-8,0.8) M4(-7.2,0.8) M5(-6.4,0.8) M6(-5.6,0.8) M7(-4.8,0.8) M8(-4,0.8) M9(-3.2,0.8) M10(-2.4,0.8) M11(-1.6,0.8) M12(-0.8,0.8) M13(0,0.8) M14(0.8,0.8) M15(1.6,0.8) M16(2.4,0.8) M17(3.2,0.8) M18(4,0.8) M19(4.8,0.8) M20(5.6,0.8) M21(6.4,0.8) M22(7.2,0.8) M23(8,0.8) M24(8.8,0.8) M25(9.6,0.8) N1(-9.6,0) N2(-8.8,0) N3(-8,0) N4(-7.2,0) N5(-6.4,0) N6(-5.6,0) N7(-4.8,0) N8(-4,0) N9(-3.2,0) N10(-2.4,0) N11(-1.6,0) N12(-0.8,0) N13(0,0) N14(0.8,0) N15(1.6,0) N16(2.4,0) N17(3.2,0) N18(4,0) N19(4.8,0) N20(5.6,0) N21(6.4,0) N22(7.2,0) N23(8,0) N24(8.8,0) N25(9.6,0) P1(-9.6,-0.8) P2(-8.8,-0.8) P3(-8,-0.8) P4(-7.2,-0.8) P5(-6.4,-0.8) P6(-5.6,-0.8) P7(-4.8,-0.8) P8(-4,-0.8) P9(-3.2,-0.8) P10(-2.4,-0.8) P11(-1.6,-0.8) P12(-0.8,-0.8) P13(0,-0.8) P14(0.8,-0.8) P15(1.6,-0.8) P16(2.4,-0.8) P17(3.2,-0.8) P18(4,-0.8) P19(4.8,-0.8) P20(5.6,-0.8) P21(6.4,-0.8) P22(7.2,-0.8) P23(8,-0.8) P24(8.8,-0.8) P25(9.6,-0.8) R1(-9.6,-1.6) R2(-8.8,-1.6) R3(-8,-1.6) R4(-7.2,-1.6) R5(-6.4,-1.6) R6(-5.6,-1.6) R7(-4.8,-1.6) R8(-4,-1.6) R9(-3.2,-1.6) R10(-2.4,-1.6) R11(-1.6,-1.6) R12(-0.8,-1.6) R13(0,-1.6) R14(0.8,-1.6) R15(1.6,-1.6) R16(2.4,-1.6) R17(3.2,-1.6) R18(4,-1.6) R19(4.8,-1.6) R20(5.6,-1.6) R21(6.4,-1.6) R22(7.2,-1.6) R23(8,-1.6) R24(8.8,-1.6) R25(9.6,-1.6) T1(-9.6,-2.4) T2(-8.8,-2.4) T3(-8,-2.4) T4(-7.2,-2.4) T5(-6.4,-2.4) T6(-5.6,-2.4) T7(-4.8,-2.4) T8(-4,-2.4) T9(-3.2,-2.4) T10(-2.4,-2.4) T11(-1.6,-2.4) T12(-0.8,-2.4) T13(0,-2.4) T14(0.8,-2.4) T15(1.6,-2.4) T16(2.4,-2.4) T17(3.2,-2.4) T18(4,-2.4) T19(4.8,-2.4) T20(5.6,-2.4) T21(6.4,-2.4) T22(7.2,-2.4) T23(8,-2.4) T24(8.8,-2.4) T25(9.6,-2.4) U1(-9.6,-3.2) U2(-8.8,-3.2) U3(-8,-3.2) U4(-7.2,-3.2) U5(-6.4,-3.2) U6(-5.6,-3.2) U7(-4.8,-3.2) U8(-4,-3.2) U9(-3.2,-3.2) U10(-2.4,-3.2) U11(-1.6,-3.2) U12(-0.8,-3.2) U13(0,-3.2) U14(0.8,-3.2) U15(1.6,-3.2) U16(2.4,-3.2) U17(3.2,-3.2) U18(4,-3.2) U19(4.8,-3.2) U20(5.6,-3.2) U21(6.4,-3.2) U22(7.2,-3.2) U23(8,-3.2) U24(8.8,-3.2) U25(9.6,-3.2) V1(-9.6,-4) V2(-8.8,-4) V3(-8,-4) V4(-7.2,-4) V5(-6.4,-4) V6(-5.6,-4) V7(-4.8,-4) V8(-4,-4) V9(-3.2,-4) V10(-2.4,-4) V11(-1.6,-4) V12(-0.8,-4) V13(0,-4) V14(0.8,-4) V15(1.6,-4) V16(2.4,-4) V17(3.2,-4) V18(4,-4) V19(4.8,-4) V20(5.6,-4) V21(6.4,-4) V22(7.2,-4) V23(8,-4) V24(8.8,-4) V25(9.6,-4) W1(-9.6,-4.8) W2(-8.8,-4.8) W3(-8,-4.8) W4(-7.2,-4.8) W5(-6.4,-4.8) W6(-5.6,-4.8) W7(-4.8,-4.8) W8(-4,-4.8) W9(-3.2,-4.8) W10(-2.4,-4.8) W11(-1.6,-4.8) W12(-0.8,-4.8) W13(0,-4.8) W14(0.8,-4.8) W15(1.6,-4.8) W16(2.4,-4.8) W17(3.2,-4.8) W18(4,-4.8) W19(4.8,-4.8) W20(5.6,-4.8) W21(6.4,-4.8) W22(7.2,-4.8) W23(8,-4.8) W24(8.8,-4.8) W25(9.6,-4.8) Y1(-9.6,-5.6) Y2(-8.8,-5.6) Y3(-8,-5.6) Y4(-7.2,-5.6) Y5(-6.4,-5.6) Y6(-5.6,-5.6) Y7(-4.8,-5.6) Y8(-4,-5.6) Y9(-3.2,-5.6) Y10(-2.4,-5.6) Y11(-1.6,-5.6) Y12(-0.8,-5.6) Y13(0,-5.6) Y14(0.8,-5.6) Y15(1.6,-5.6) Y16(2.4,-5.6) Y17(3.2,-5.6) Y18(4,-5.6) Y19(4.8,-5.6) Y20(5.6,-5.6) Y21(6.4,-5.6) Y22(7.2,-5.6) Y23(8,-5.6) Y24(8.8,-5.6) Y25(9.6,-5.6)
IND_SMD_5050
  oval 1.905x5.309 smd: 1(1.7,0) 2(-1.7,0)
JP254_1
  round 1.499 hole 1.016: 1(0,0)
JP254_2
  rect 1.499x1.499 hole 1.016: 1(0,0)
  round 1.499 hole 1.016: 2(0,-2.54)
JP254_3
  rect 1.499x1.499 hole 1.016: 1(0,0)
  round 1.499 hole 1.016: 2(2.54,0) 3(5.08,0)
MTH_1P2_2
  round 2.21 hole 2.21 unplated: (0,0)
OSC4_751
  rect 1.651x2.007 smd: 1(-2.54,-2.1) 2(2.54,-2.1) 3(2.54,2.1) 4(-2.54,2.1)
QFN32
  oval 0.254x0.991 smd: 1(1.75,2.6) 2(1.25,2.6) 3(0.75,2.6) 4(0.25,2.6) 5(-0.25,2.6) 6(-0.75,2.6) 7(-1.25,2.6) 8(-1.75,2.6) 17(-1.75,-2.6) 18(-1.25,-2.6) 19(-0.75,-2.6) 20(-0.25,-2.6) 21(0.25,-2.6) 22(0.75,-2.6) 23(1.25,-2.6) 24(1.75,-2.6)
  oval 0.991x0.254 smd: 9(-2.6,1.75) 10(-2.6,1.25) 11(-2.6,0.75) 12(-2.6,0.25) 13(-2.6,-0.25) 14(-2.6,-0.75) 15(-2.6,-1.25) 16(-2.6,-1.75) 25(2.6,-1.75) 26(2.6,-1.25) 27(2.6,-0.75) 28(2.6,-0.25) 29(2.6,0.25) 30(2.6,0.75) 31(2.6,1.25) 32(2.6,1.75)
  rect 1.499x1.499 smd: 33(-1,1) 34(1,1) 35(-1,-1) 36(1,-1)
R0402
  rect 0.635x0.508 smd: 1(-0.508,0) 2(0.508,0)
R0603
  rect 0.762x0.813 smd: 1(-0.762,0) 2(0.762,0)
SOD_323
  rect 0.61x0.61 smd: 1(-1.1,0) 2(1.1,0)
SOT_6
  rect 0.711x0.762 smd: 1(-0.95,-1.45) 2(0,-1.45) 3(0.95,-1.45) 4(0.95,1.45) 5(0,1.45) 6(-0.95,1.45)
  rect 2.591x1.651 smd: 7(0,0)
SOT_23
  rect 0.889x0.889 smd: 1(-0.95,-1) 2(0.95,-1)
  rect 0.889x1.27 smd: 3(0,1)
TACT_4P_PUSHON
  rect 2.007x1.194 smd: 1(-4.4,2.25) 2(-4.4,-2.25) 3(4.4,2.25) 4(4.4,-2.25)
TESTPOINT
  round 0.991 smd: 1(0,0)
unnamed
  round 1.194 smd: 1(0,0)

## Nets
1V1: C265.2 FB1.1 R67.1 R83.1
1V3_CORE: C218.2 C219.2 C220.2 C221.2 C222.2 R1.1
1V3_CORE23: C226.2 C227.2 C228.2 C229.2 C230.2 L8.2 R2.1 R205.2 TP23.1
1V3_SOC: C234.2 C235.2 C236.2 C237.2 R3.1 R209.2
1V5: C242.2 C243.2 C244.2 C245.2 C246.2 L10.2 R17.2 R213.2 TP26.1
1V8: C208.2 C209.2 C258.2 C259.2 C260.2 C261.2 FB5.2 J5.13 J5.14 R24.1 R26.1 R28.1
2V5: R61.1 R68.1 R84.1
3V3: C166.2 C203.2 C204.2 C210.2 C250.2 C251.2 C252.2 C253.2 C254.2 C263.2 FB2.1 FB3.2 FB4.1 J5.9 J5.10 J7.15 L11.2 R4.1 R23.1 R25.1 R27.1 R29.1 R46.1 R60.1 R64.1 R66.1 R89.1 R90.1 R194.1 R199.2 R200.1 R217.2 TP28.1
5V_VGA: C190.2 C191.2 C192.2 D8.2 D9.2 J5.65 J7.18 R160.2 R162.2
AGND: C196.1 C197.1 C198.1 C200.1 C201.1 J5.67 J7.37 R163.1 U15.2 U15.28
GND: C1.1 C2.1 C3.1 C4.1 C5.1 C6.1 C7.1 C8.1 C9.1 C10.1 C11.1 C12.1 C13.1 C14.1 C15.1 C16.1 C17.1 C18.1 C19.1 C20.1 C21.1 C22.1 C23.1 C24.1 C25.1 C26.1 C27.1 C28.1 C29.1 C31.1 C32.1 C33.1 C34.1 C35.1 C36.1 C37.1 C38.1 C39.1 C41.1 C42.1 C44.1 C47.1 C48.1 C49.1 C50.1 C52.1 C53.1 C54.1 C55.1 C56.1 C57.1 C58.1 C59.1 C60.1 C61.1 C62.1 C63.1 C64.1 C65.1 C66.1 C67.1 C68.1 C69.1 C70.1 C71.1 C72.1 C73.1 C74.1 C75.1 C76.1 C77.1 C78.1 C79.1 C80.1 C81.1 C82.1 C83.1 C84.1 C85.1 C86.1 C87.1 C88.1 C89.1 C90.1 C91.1 C92.1 C93.1 C94.1 C95.1 C99.1 C100.1 C101.1 C102.1 C103.1 C104.1 C105.1 C106.1 C107.1 C108.1 C109.1 C110.1 C111.1 C112.1 C113.1 C114.1 C115.1 C116.1 C117.1 C118.1 C120.1 C122.1 C124.1 C126.1 C127.1 C128.1 C129.1 C130.1 C131.1 C132.1 C133.1 C134.1 C135.1 C136.1 C137.1 C138.1 C139.1 C140.1 C141.1 C144.1 C145.1 C152.1 C153.1 C154.1 C155.1 C156.1 C157.1 C158.1 C160.1 C161.1 C162.1 C163.1 C164.1 C165.1 C166.1 C167.1 C168.1 C175.1 C176.1 C177.1 C178.1 C179.1 C180.1 C181.1 C182.1 C183.1 C184.1 C185.1 C186.1 C190.1 C191.1 C192.1 C193.1 C194.1 C195.1 C202.1 C203.1 C204.1 C205.1 C206.1 C207.1 C208.1 C209.1 C210.1 C211.1 C212.1 C213.1 C214.1 C215.1 C218.1 C219.1 C220.1 C221.1 C223.1 C224.1 C225.1 C226.1 C227.1 C228.1 C229.1 C231.1 C234.1 C235.1 C236.1 C237.1 C239.1 C240.1 C241.1 C242.1 C243.1 C244.1 C245.1 C247.1 C248.1 C249.1 C250.1 C251.1 C252.1 C253.1 C255.1 C257.1 C258.1 C259.1 C260.1 C261.1 C263.1 C265.1 D8.1 D9.1 D10.1 J5.5 J5.6 J5.7 J5.8 J5.11 J5.12 J5.23 J5.24 J5.43 J5.60 J5.66 J5.80 J6.5 J6.6 J6.10 J6.16 J6.25 J6.26 J6.37 J6.38 J6.63 J6.64 J7.2 J7.5 J7.14 J7.23 J7.25 J7.27 J7.29 J7.32 J7.35 J7.41 J7.42 J10.1 Q1.2 Q6.2 Q7.2 Q8.2 Q9.2 R9.1 R10.1 R11.1 R12.1 R13.2 R14.2 R16.1 R39.2 R50.1 R77.2 R93.2 R107.1 R108.1 R109.1 R110.1 R111.1 R112.1 R113.1 R114.1 R116.1 R118.1 R119.1 R120.1 R121.1 R125.1 R127.1 R128.1 R130.1 R133.1 R134.1 R136.1 R137.1 R152.1 R153.1 R154.1 R155.1 R156.1 R157.1 R163.2 R196.1 R204.1 R206.2 R208.1 R212.1 R214.2 R216.1 R218.2 R220.1 R222.2 R224.2 TP3.1 TP10.1 TP12.1 TP30.1 U1.A4 U1.A8 U1.A13 U1.A25 U1.AA7 U1.AA10 U1.AA13 U1.AA16 U1.AA19 U1.AA22 U1.AB3 U1.AB24 U1.AD4 U1.AD7 U1.AD10 U1.AD13 U1.AD16 U1.AD19 U1.AD22 U1.AE1 U1.AE25 U1.B4 U1.C1 U1.C4 U1.C6 U1.C10 U1.D3 U1.D6 U1.D8 U1.E5 U1.E6 U1.E7 U1.F5 U1.F6 U1.F7 U1.F8 U1.G3 U1.G10 U1.G19 U1.H8 U1.H12 U1.H15 U1.H18 U1.J2 U1.J8 U1.J12 U1.J15 U1.J18 U1.K8 U1.K10 U1.K12 U1.K15 U1.K18 U1.L2 U1.L5 U1.L8 U1.L10 U1.L12 U1.L15 U1.L18 U1.M8 U1.M10 U1.M12 U1.M15 U1.M18 U1.N8 U1.N10 U1.N15 U1.N18 U1.P8 U1.P10 U1.P12 U1.P15 U1.P18 U1.R8 U1.R12 U1.R15 U1.R17 U1.T8 U1.T11 U1.T12 U1.T15 U1.T17 U1.T19 U1.U8 U1.U11 U1.U12 U1.U15 U1.U17 U1.U19 U1.V8 U1.V19 U1.W3 U1.W7 U1.W8 U1.W9 U1.W10 U1.W11 U1.W12 U1.W13 U1.W15 U1.W16 U1.W17 U1.W18 U1.W19 U1.Y5 U1.Y24 U2.A9 U2.B1 U2.B3 U2.B9 U2.D1 U2.D8 U2.E1 U2.E2 U2.E8 U2.F9 U2.G1 U2.G8 U2.G9 U2.J2 U2.J8 U2.M1 U2.M9 U2.P1 U2.P9 U2.T1 U2.T9 U3.A9 U3.B1 U3.B3 U3.B9 U3.D1 U3.D8 U3.E1 U3.E2 U3.E8 U3.F9 U3.G1 U3.G8 U3.G9 U3.J2 U3.J8 U3.M1 U3.M9 U3.P1 U3.P9 U3.T1 U3.T9 U4.A9 U4.B1 U4.B3 U4.B9 U4.D1 U4.D8 U4.E1 U4.E2 U4.E8 U4.F9 U4.G1 U4.G8 U4.G9 U4.J2 U4.J8 U4.M1 U4.M9 U4.P1 U4.P9 U4.T1 U4.T9 U5.A9 U5.B1 U5.B3 U5.B9 U5.D1 U5.D8 U5.E1 U5.E2 U5.E8 U5.F9 U5.G1 U5.G8 U5.G9 U5.J2 U5.J8 U5.M1 U5.M9 U5.P1 U5.P9 U5.T1 U5.T9 U11.1 U15.12 U15.24 U15.33 U15.34 U15.35 U16.2 U19.2 U19.5 U19.11 U19.12 U19.13 U19.14 U21.2 U21.5 U21.11 U21.12 U21.13 U21.14 U22.2 U22.5 U22.11 U22.12 U22.13 U22.14
VCC_5V: C167.2 C205.2 C206.2 C207.2 C211.2 J5.1 J5.2 J5.3 J5.4 J8.1 J9.1 Q5.1 Q5.2 Q5.3 Q5.5 Q5.6 R192.1 S1.1 S1.3 U11.3
VCC_DDR: C15.2 C16.2 C21.2 C22.2 C27.2 C28.2 C33.2 C34.2 C39.2 C51.2 C53.2 C54.2 C55.2 C56.2 C57.2 C58.2 C59.2 C60.2 C61.2 C62.2 C63.2 C64.2 C65.2 C66.2 C67.2 C68.2 C69.2 C70.2 C71.2 C72.2 C73.2 C74.2 C75.2 C76.2 C77.2 C78.2 C79.2 C80.2 C81.2 C82.2 C83.2 C84.2 C85.2 C86.2 C87.2 C88.2 C89.2 C90.2 C91.2 C92.2 C93.2 C94.2 C95.2 C99.2 R15.2 R17.1 R65.1 TP9.1 U1.R18 U1.T18 U1.U18 U1.V9 U1.V10 U1.V11 U1.V12 U1.V13 U1.V14 U1.V15 U1.V16 U1.V17 U1.V18 U2.A1 U2.A8 U2.B2 U2.C1 U2.C9 U2.D2 U2.D9 U2.E9 U2.F1 U2.G7 U2.H2 U2.H9 U2.K2 U2.K8 U2.N1 U2.N9 U2.R1 U2.R9 U3.A1 U3.A8 U3.B2 U3.C1 U3.C9 U3.D2 U3.D9 U3.E9 U3.F1 U3.G7 U3.H2 U3.H9 U3.K2 U3.K8 U3.N1 U3.N9 U3.R1 U3.R9 U4.A1 U4.A8 U4.B2 U4.C1 U4.C9 U4.D2 U4.D9 U4.E9 U4.F1 U4.G7 U4.H2 U4.H9 U4.K2 U4.K8 U4.N1 U4.N9 U4.R1 U4.R9 U5.A1 U5.A8 U5.B2 U5.C1 U5.C9 U5.D2 U5.D9 U5.E9 U5.F1 U5.G7 U5.H2 U5.H9 U5.K2 U5.K8 U5.N1 U5.N9 U5.R1 U5.R9
VCC_EIM: C115.2 C116.2 C117.2 C118.2 J1.2 J1.4 J1.6 J1.8 J1.10 J1.12 J1.14 J1.16 R40.2 R41.2 R45.2 R46.2 R53.2 R148.1 U1.K19 U1.L19 U1.M19
VCC_FEC: C130.2 C144.2 C145.2 R64.2 R70.2 R71.2 U1.R19
VCC_GPIO: C162.2 R89.2 R96.1 R97.1 R98.1 R99.1 U1.P7
VCC_JTAG: C132.2 J7.6 R66.2 U1.J7
VCC_MIPI: C120.2 U1.K7
VCC_NAND: C103.2 C104.2 C105.2 C106.2 C107.2 C108.2 C109.2 C112.2 C113.2 C114.2 R29.2 R30.2 R33.1 R34.2 R35.2 R36.2 R37.2 R38.2 U1.G15
VCC_RGMII: C131.2 R65.2 U1.G18
VCC_SD1: C100.2 R23.2 R24.2 U1.G16
VCC_SD2: C101.2 R25.2 R26.2 U1.G17
VCC_SD3: C102.2 R27.2 R28.2 R44.2 U1.G14
VCC_SYS: C212.2 C213.2 C224.2 C225.2 C240.2 C241.2 C248.2 C249.2 C257.2 J8.2 Q5.7 R198.1 U19.6 U19.7 U19.8 U21.6 U21.7 U21.8 U22.6 U22.7 U22.8
VDD_USB: C153.2 C154.2 U1.F9
VDDA_ADU: C197.2 C198.2 FB5.1 U15.31
VDDA_FEC: C139.2 C140.2 C141.2 FB2.2 R82.2
VDDA_VGA: C173.1 C174.1 C175.2 C176.2 C177.2 FB3.1
VDDARM: C6.2 C7.2 C8.2 C9.2 TP1.1 U1.H13 U1.J13 U1.K13 U1.L13 U1.M13 U1.N13 U1.P13 U1.R13
VDDARM23: C17.2 C18.2 C19.2 C20.2 U1.H11 U1.J11 U1.K11 U1.L11 U1.M11 U1.N11 U1.P11 U1.R11
VDDARM23_IN: C12.2 C13.2 C14.2 R2.2 U1.K9 U1.L9 U1.M9 U1.N9 U1.P9 U1.R9 U1.T9 U1.U9
VDDARM_IN: C1.2 C2.2 C3.2 R1.2 U1.H14 U1.J14 U1.K14 U1.L14 U1.M14 U1.N14 U1.P14 U1.R14
VDDHIGH_2V5: C44.2 U1.H10 U1.J10
VDDHIGH_IN: C41.2 C42.2 R4.2 U1.H9 U1.J9
VDDIO_ADU: C193.2 C194.2 C195.2 C202.2 FB4.2 U15.13 U15.14 U16.4
VDDPU: C29.2 C31.2 C32.2 U1.H17 U1.J17 U1.K17 U1.L17 U1.M17 U1.N17 U1.P17
VDDSOC: C35.2 C36.2 C37.2 C38.2 TP5.1 U1.N12 U1.R10 U1.T10 U1.T13 U1.T14 U1.U10 U1.U13 U1.U14
VDDSOC_IN: C23.2 C24.2 C25.2 C26.2 R3.2 U1.H16 U1.J16 U1.K16 U1.L16 U1.M16 U1.N16 U1.P16 U1.R16 U1.T16 U1.U16
$$$125: D3.1 R90.2
$$$1686: J6.78
$$$2022: R11.2 U4.L8
$$$2023: R12.2 U5.L8
$$$3088: TP17.1 U15.26
$$$3367: R226.1 U1.V22
$$$3962: TP18.1 U15.25
$$$3964: TP19.1 U15.23
$$$3967: TP20.1 U15.21
$$$3970: TP21.1 U15.22
$$$6664: J3.3 R153.2
$$$6667: J3.1 R150.1
$$$6671: J4.3 R154.2
$$$6703: J4.1 R151.1
$$$7137: U1.B5
$$$7141: U1.A5
$$$7162: R116.2 R142.1
$$$7169: J1.15 R118.2 R144.1
$$$7174: J1.13 R119.2 R145.1
$$$7178: J1.11 R120.2 R146.1
$$$7181: J1.9 R121.2 R147.1
$$$7221: J1.1 R114.2 R141.1
$$$7224: J1.3 R113.2 R140.1
$$$7229: J1.5 R112.2 R139.1
$$$7232: J1.7 R111.2 R138.1
$$$7260: U1.C14
$$$8734: U1.D12
$$$8800: U1.F11
$$$9280: J2.1 R149.1
$$$9284: J2.3 R152.2
$$$9305: R14.1 U1.AE17
$$$9613: R164.1 U16.3
$$$10003: R93.1 U1.E12
$$$10496: R53.1
$$$12428: C173.2
$$$12438: C174.2
$$$12534: R50.2 U1.D4
$$$12536: U1.G4
$$$12539: U1.J1
$$$12609: C168.2 R92.1 U11.2
$$$13304: C179.2 L1.2 L2.1
$$$13768: Q5.4 Q6.3 Q7.3 Q8.3 R192.2
$$$13792: C182.2 L3.2 L4.1
$$$13802: C185.2 L5.2 L6.1
$$$14220: C222.1
$$$14425: R204.2
$$$14478: Q7.1 R197.1
$$$14580: C223.2
$$$15208: L8.1 U19.3 U19.4
$$$15209: C230.1 R205.1 R206.1 U19.9
$$$15210: R208.2 U19.1
$$$15211: R207.2 U19.10
$$$15212: C231.2 R207.1
$$$15333: L10.1 U21.3 U21.4
$$$15334: C246.1 R213.1 R214.1 U21.9
$$$15335: R216.2 U21.1
$$$15336: R215.2 U21.10
$$$15337: C247.2 R215.1
$$$15338: L11.1 U22.3 U22.4
$$$15339: C254.1 R217.1 R218.1 U22.9
$$$15340: R220.2 U22.1
$$$15341: R219.2 U22.10
$$$15342: C255.2 R219.1
$$$15778: R77.1
$$$16549: R209.1
$$$16550: R212.2
$$$16552: C239.2
$$$16807: U1.A2
$$$17664: Q3.1 R159.2
$$$17806: U1.B7
$$$17810: U1.A7
$$$18017: Q4.1 R161.2
$$$18082: C110.2 R33.2
$$$18139: U1.D9
$$$18147: U1.C9
$$$18218: C111.2
$$$18262: J7.3 R186.2
$$$18265: J7.4 R187.2
$$$19166: J7.30 R188.2
$$$19169: J7.31 R189.2
$$$19172: J7.33 R190.2
$$$19175: J7.34 R191.2
$$$22462: R222.1
$$$22838: Q6.1 R193.2
$$$22839: C214.2 R193.1 R195.1 S1.2 S1.4
$$$22840: Q9.1 R195.2
$$$22841: C215.2 D11.2 D12.2 R199.1
$$$24067: R226.2
$$$26032: C159.1 R88.2
$$$26035: Q1.3 R87.1 R88.1
$$$26134: C160.2
$$$26219: U1.D14
$$$26224: R22.1 U1.E16
$$$26282: R20.1 U1.D20
$$$28283: U1.C5
$$$28284: U1.D5
$$$29221: R9.2 U2.L8
$$$29803: D10.2 R198.2
$$$30694: R10.2 U3.L8
$$$32027: C201.2 U15.18
$$$32057: C196.2 U15.27
$$$32498: C200.2 R165.2 U15.32
$$$32507: C199.2 U15.1
AUD3_RXD: U1.N3 U15.10
AUD3_TXC: U1.N1 U15.8
AUD3_TXD: U1.P2 U15.9
AUD3_TXFS: U1.N4 U15.7
AUD4_RXC: J5.37 U1.F19
AUD4_RXD: J5.39 U1.A22
AUD4_RXFS: J5.38 U1.C21
AUD4_TXC: J5.42 U1.B22
AUD4_TXD: J5.41 U1.A23
AUD4_TXFS: J5.40 U1.E20
BATTERY: D3.2
BOOT_MODE0: J4.2 U1.C12
BOOT_MODE1: J3.2 U1.F12
CAN1_RX: J6.80 U1.W4
CAN1_TX: J6.79 U1.W6
CLKO1: J6.77 U1.T5
CLKO2: R223.1 U1.R7
CSI0_DAT12: J6.53 U1.M2
CSI0_DAT13: J6.54 U1.L1
CSI0_DAT14: J6.55 U1.M4
CSI0_DAT15: J6.56 U1.M5
CSI0_DAT16: J6.57 U1.L4
CSI0_DAT17: J6.58 U1.L3
CSI0_DAT18: J6.59 U1.M6
CSI0_DAT19: J6.60 U1.L6
CSI0_ENABLE: J6.51 U1.P3
CSI0_HSYNC: J6.50 U1.P4
CSI0_PIXCLK: J6.49 U1.P1
CSI0_VSYNC: J6.52 U1.N2
CSI_CLK0M: U1.F4
CSI_CLK0P: U1.F3
CSI_D0M: U1.E4
CSI_D0P: U1.E3
CSI_D1M: U1.D1
CSI_D1P: U1.D2
CSI_D2M: U1.E1
CSI_D2P: U1.E2
CSI_D3M: U1.F2
CSI_D3P: U1.F1
CSPI1_MISO: U1.F21
CSPI1_MOSI: U1.D24
CSPI1_SCLK: U1.C25
CSPI2_MISO: J5.48 U1.J24
CSPI2_MOSI: J5.49 U1.J23
CSPI2_SCLK: J5.46 U1.H24
CSPI2_SSS0: J5.47
CSPI2_SSS1: J5.45
DDC_SCL: J5.64 J7.19 Q4.3 R162.1
DDC_SDA: J5.63 J7.20 Q3.3 R160.1
DDR_VREF: C4.2 C5.2 C10.2 C11.2 C47.2 C48.2 C49.2 C50.2 C51.1 C52.2 R15.1 R16.2 TP11.1 U1.AC2 U2.H1 U2.M8 U3.H1 U3.M8 U4.H1 U4.M8 U5.H1 U5.M8
DISP0_DAT00: U1.P24
DISP0_DAT01: U1.P22
DISP0_DAT02: U1.P23
DISP0_DAT03: U1.P21
DISP0_DAT04: U1.P20
DISP0_DAT05: U1.R25
DISP0_DAT06: U1.R23
DISP0_DAT07: U1.R24
DISP0_DAT08: U1.R22
DISP0_DAT09: U1.T25
DISP0_DAT10: U1.R21
DISP0_DAT11: U1.T23
DISP0_DAT12: U1.T24
DISP0_DAT13: U1.R20
DISP0_DAT14: U1.U25
DISP0_DAT15: U1.T22
DISP0_DAT16: U1.T21
DISP0_DAT17: U1.U24
DISP0_DAT18: U1.V25
DISP0_DAT19: U1.U23
DISP0_DAT20: U1.U22
DISP0_DAT21: U1.T20
DISP0_DAT22: U1.V24
DISP0_DAT23: U1.W24
DISP0_HSYNC: U1.N25
DISP0_PIXCLK: U1.N19
DISP0_READY: U1.N21
DISP0_STBY#: U1.P25
DISP0_VSYNC: U1.N20
DRAM_A0: U1.AC14 U2.N3 U3.N3 U4.N3 U5.N3
DRAM_A1: U1.AB14 U2.P7 U3.P7 U4.P7 U5.P7
DRAM_A2: U1.AA14 U2.P3 U3.P3 U4.P3 U5.P3
DRAM_A3: U1.Y14 U2.N2 U3.N2 U4.N2 U5.N2
DRAM_A4: U1.W14 U2.P8 U3.P8 U4.P8 U5.P8
DRAM_A5: U1.AE13 U2.P2 U3.P2 U4.P2 U5.P2
DRAM_A6: U1.AC13 U2.R8 U3.R8 U4.R8 U5.R8
DRAM_A7: U1.Y13 U2.R2 U3.R2 U4.R2 U5.R2
DRAM_A8: U1.AB13 U2.T8 U3.T8 U4.T8 U5.T8
DRAM_A9: U1.AE12 U2.R3 U3.R3 U4.R3 U5.R3
DRAM_A10: U1.AA15 U2.L7 U3.L7 U4.L7 U5.L7
DRAM_A11: U1.AC12 U2.R7 U3.R7 U4.R7 U5.R7
DRAM_A12: U1.AD12 U2.N7 U3.N7 U4.N7 U5.N7
DRAM_A13: U1.AC17 U2.T3 U3.T3 U4.T3 U5.T3
DRAM_A14: U1.AA12 U2.T7 U3.T7 U4.T7 U5.T7
DRAM_A15: U1.Y12 U2.M7 U3.M7 U4.M7 U5.M7
DRAM_BA0: U1.AC15 U2.M2 U3.M2 U4.M2 U5.M2
DRAM_BA1: U1.Y15 U2.N8 U3.N8 U4.N8 U5.N8
